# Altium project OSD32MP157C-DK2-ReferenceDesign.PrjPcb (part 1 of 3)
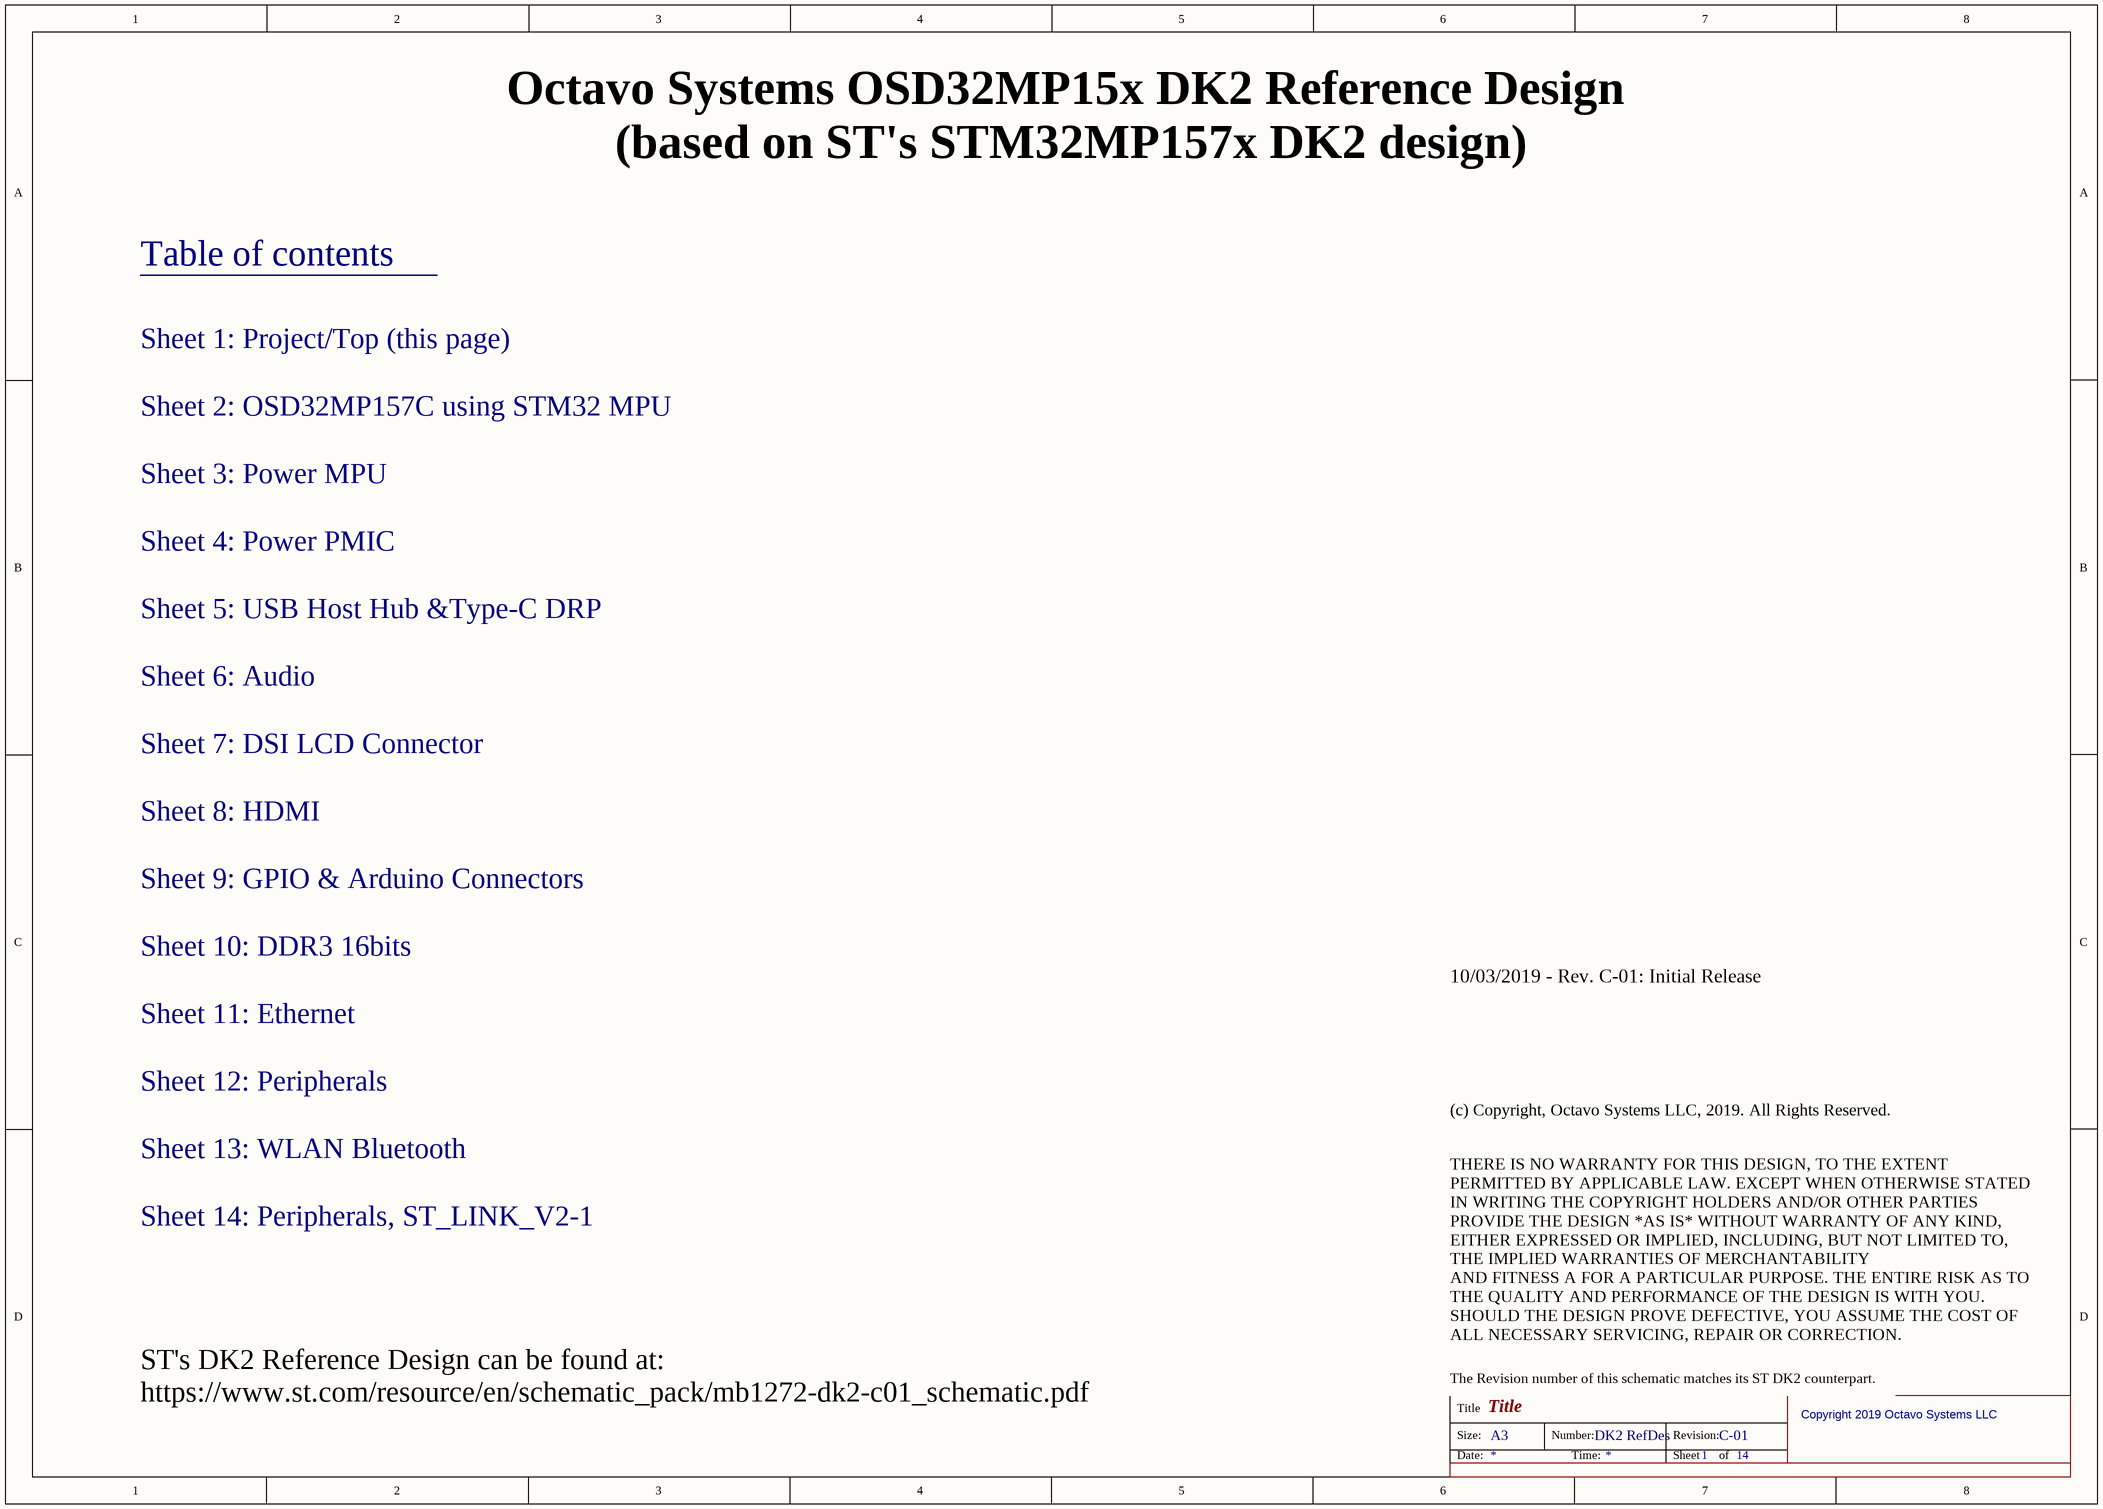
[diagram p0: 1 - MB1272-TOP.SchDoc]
14 sheets, 409 parts. Net scope: flat (ports and power ports of the same name join across sheets).
Board file: OSD32MP157C_DK2-0071_01232019RELEASE.PcbDoc
Sheets:
  1 - MB1272-TOP.SchDoc
  2 - OSD32MP157C_18x18.SchDoc
  3 - Power_MPU.SchDoc
  4 - PMIC.SchDoc
  5 - USB_Host_Hub&TypeC_DRP.SchDoc
  6 - AUDIO.SchDoc
  7 - DSI_LCD.SchDoc
  8 - HDMI.SchDoc
  9 - GPIO_&_Arduino_ Connectors.SchDoc
  10 - DDR3_16bits.SchDoc
  11 - Ethernet.SchDoc
  12 -  Peripherals.SchDoc
  13 - WLAN_BLUETOOTH.SchDoc
  14 -ST_LINK_V2-1.SCHDOC

## Sheet 1 - MB1272-TOP.SchDoc: Title
size A3; CompanyName: Octavo Systems; Address3: Austin, TX; Address4: USA; DocumentNumber: DK2 RefDes; Revision: C-01; SheetNumber: 1; SheetTotal: 14

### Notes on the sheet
- Octavo Systems OSD32MP15x DK2 Reference Design
  (based on ST's STM32MP157x DK2 design)
- Table of contents
- Sheet 1: Project/Top (this page)
- Sheet 2: OSD32MP157C using STM32 MPU
- Sheet 3: Power MPU
- Sheet 4: Power PMIC
- Sheet 5: USB Host Hub &Type-C DRP
- Sheet 6: Audio
- Sheet 7: DSI LCD Connector
- Sheet 8: HDMI
- Sheet 9: GPIO & Arduino Connectors
- Sheet 10: DDR3 16bits
- Sheet 11: Ethernet
- Sheet 12: Peripherals
- (c) Copyright, Octavo Systems LLC, 2019. All Rights Reserved.
- 10/03/2019 - Rev. C-01: Initial Release
- Sheet 13: WLAN Bluetooth
- Sheet 14: Peripherals, ST_LINK_V2-1
- THERE IS NO WARRANTY FOR THIS DESIGN, TO THE EXTENT PERMITTED BY APPLICABLE LAW. EXCEPT WHEN OTHERWISE STATED IN WRITING THE COPYRIGHT HOLDERS AND/OR OTHER PARTIES PROVIDE THE DESIGN *AS IS* WITHOUT WARRANTY OF ANY KIND, EITHER EXPRESSED OR IMPLIED, INCLUDING, BUT NOT LIMITED TO, THE IMPLIED WARRANTIES OF MERCHANTABILITY
  AND FITNESS A FOR A PARTICULAR PURPOSE. THE ENTIRE RISK AS TO THE QUALITY AND PERFORMANCE OF THE DESIGN IS WITH YOU. SHOULD THE DESIGN PROVE DEFECTIVE, YOU ASSUME THE COST OF ALL NECESSARY SERVICING, REPAIR OR CORRECTION.
- The Revision number of this schematic matches its ST DK2 counterpart.
- ST's DK2 Reference Design can be found at: https://www.st.com/resource/en/schematic_pack/mb1272-dk2-c01_schematic.pdf
- Copyright 2019 Octavo Systems LLC

## Sheet 2 - OSD32MP157C_18x18.SchDoc: MPU_18x18 IO
size A3; DocumentNumber: DK2 RefDes; Revision: C-01; SheetNumber: 2; SheetTotal: 14
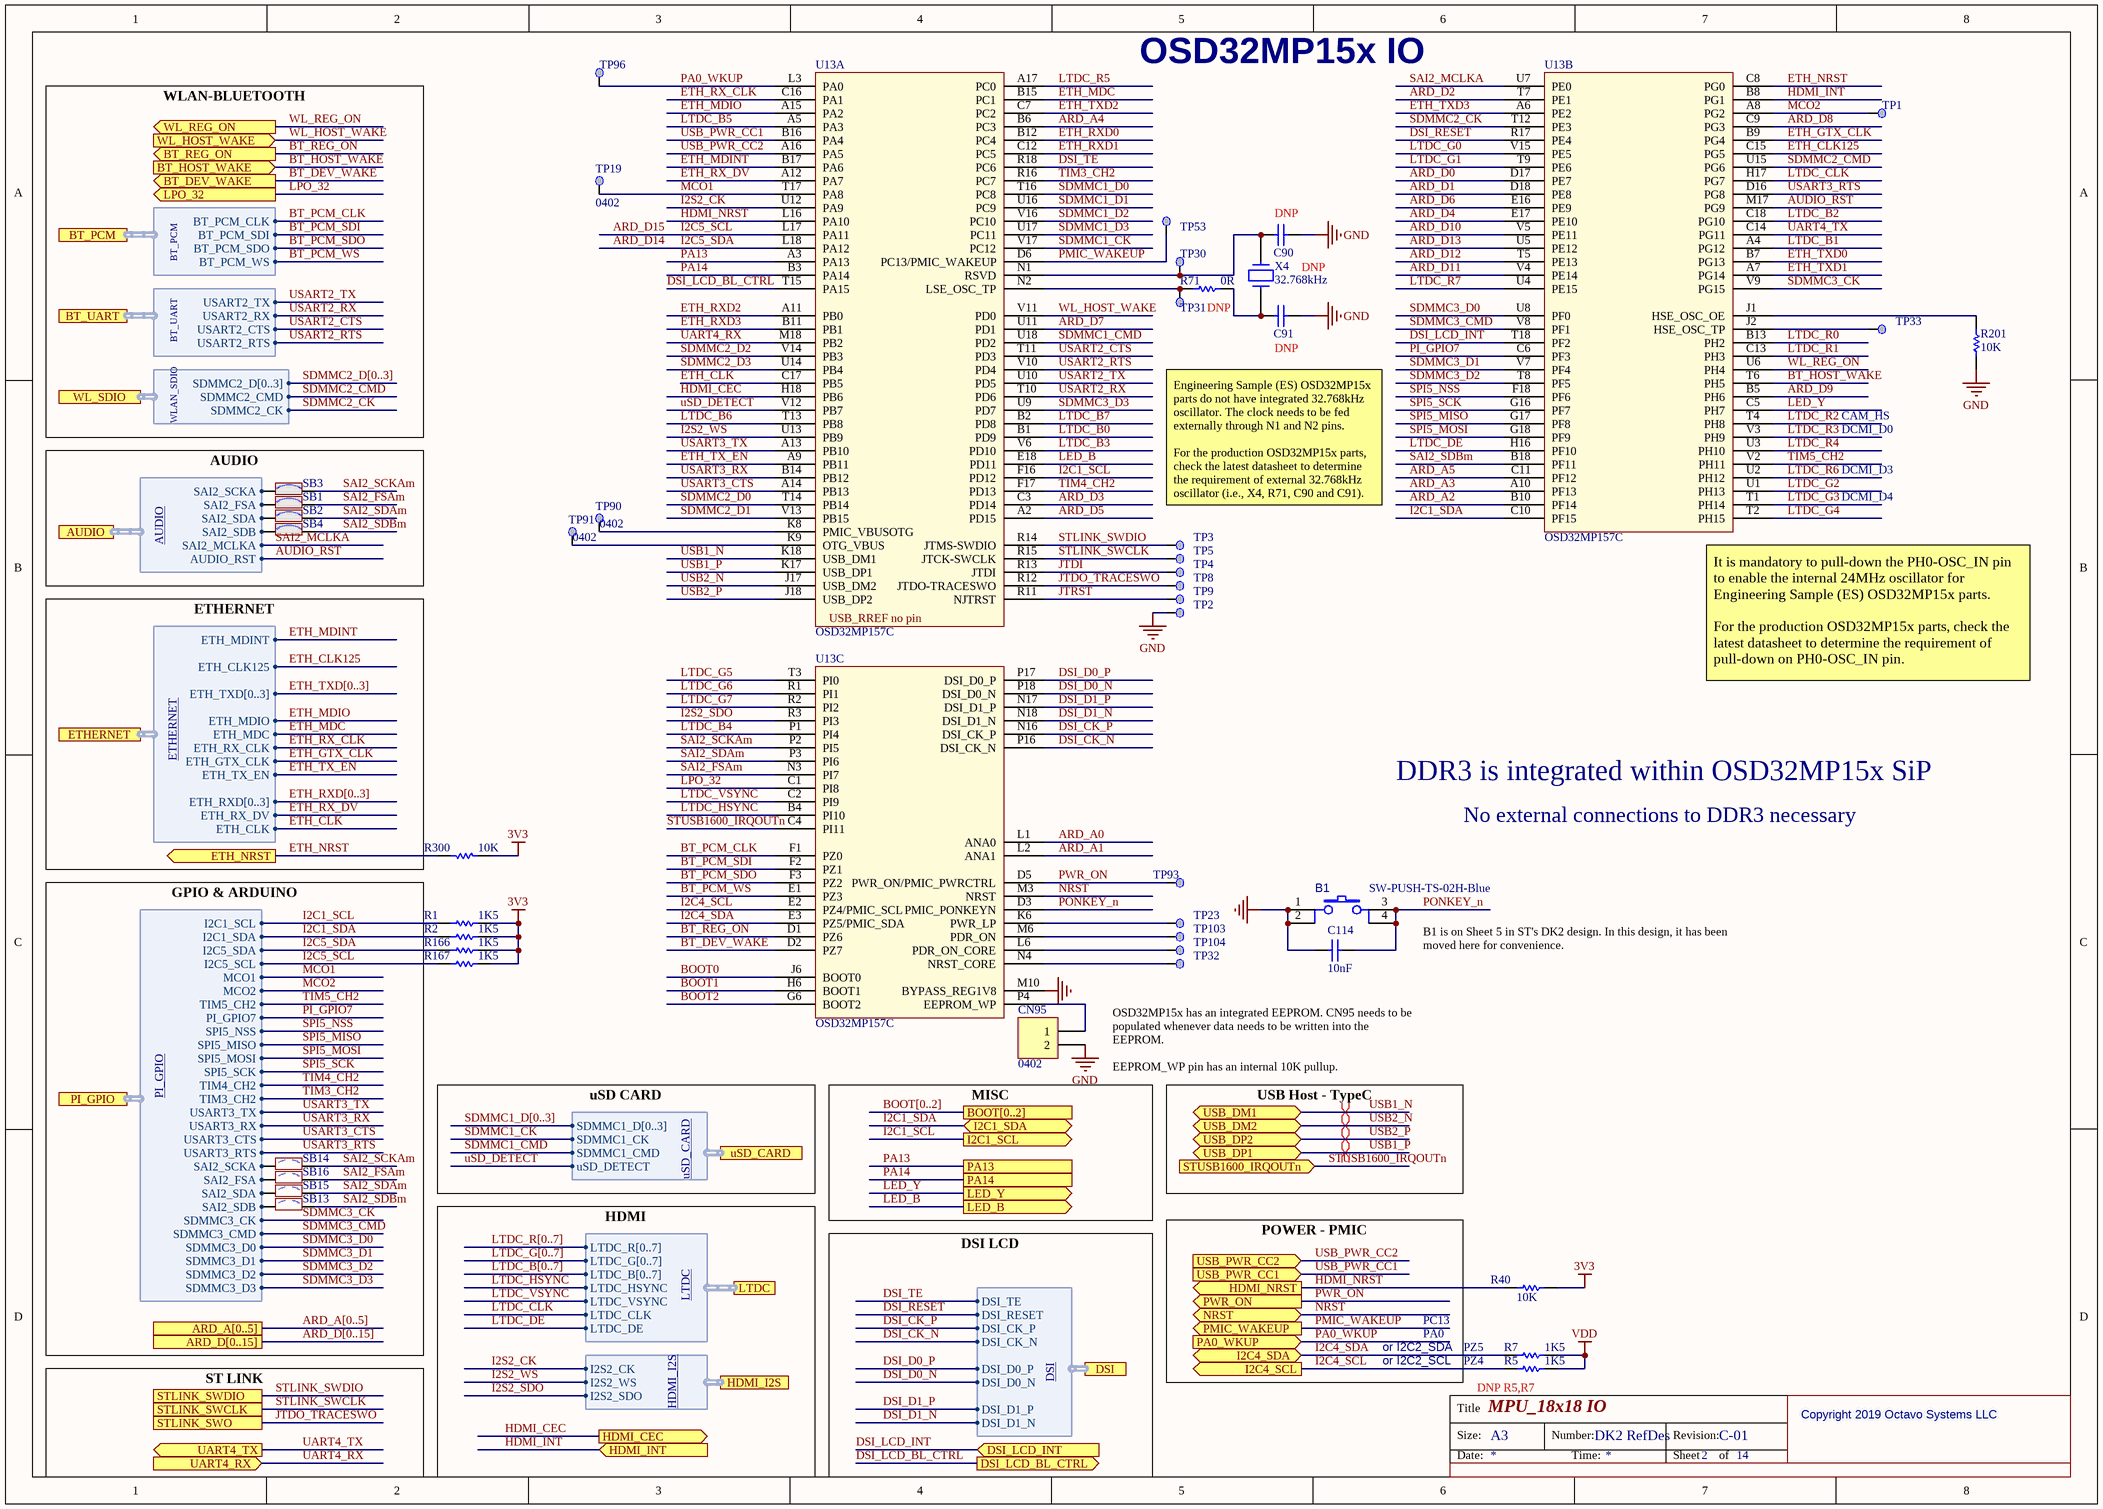
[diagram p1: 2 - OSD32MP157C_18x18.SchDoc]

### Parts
B1  value SW-PUSH-TS-02H-Blue  [SWI_JIUBABA_C-TS-02H-2-5-B-V-T_R_BLUE]
C90  Capacitor  [C0402]  (value not drawn)  (no BOM)
C91  Capacitor  [C0402]  (value not drawn)  (no BOM)
C114  value 10nF  [C0402]
CN95  0402  [MHDR1X2]
R1  value 1K5  [R0402]
R2  value 1K5  [R0402]
R5  value 1K5  [R0402]  (no BOM)
R7  value 1K5  [R0402]  (no BOM)
R40  value 10K  [R0402]  (hidden comment: Resistor)
R71  value 0R  [R0402]
R166  value 1K5  [R0402]
R167  value 1K5  [R0402]
R201  value 10K  [R0402]
R300  value 10K  [R0402]  (hidden comment: Resistor)
SB1  (no value)  [SOLDER-BRIDGE_R0603-0R]
SB2  (no value)  [SOLDER-BRIDGE_R0603-0R]
SB3  (no value)  [SOLDER-BRIDGE_R0603-0R]
SB4  (no value)  [SOLDER-BRIDGE_R0603-0R]
SB13  (no value)  [SOLDER-BRIDGE_R0603-0R]
SB14  (no value)  [SOLDER-BRIDGE_R0603-0R]
SB15  (no value)  [SOLDER-BRIDGE_R0603-0R]
SB16  (no value)  [SOLDER-BRIDGE_R0603-0R]
TP1  Test Point  [TP_SMD_1MM]  (value not drawn)  (no BOM)
TP2  Test Point  [TP_SMD_1MM]  (value not drawn)  (no BOM)
TP3  Test Point  [TP_SMD_1MM]  (value not drawn)  (no BOM)
TP4  Test Point  [TP_SMD_1MM]  (value not drawn)  (no BOM)
TP5  Test Point  [TP_SMD_1MM]  (value not drawn)  (no BOM)
TP8  Test Point  [TP_SMD_1MM]  (value not drawn)  (no BOM)
TP9  Test Point  [TP_SMD_1MM]  (value not drawn)  (no BOM)
TP19  0402  [TP]
TP23  Test Point  [TP_SMD_1MM]  (value not drawn)  (no BOM)
TP30  Test Point  [TP_SMD_1MM]  (value not drawn)  (no BOM)
TP31  Test Point  [TP_SMD_1MM]  (value not drawn)  (no BOM)
TP32  Test Point  [TP_SMD_1MM]  (value not drawn)  (no BOM)
TP33  Test Point  [TP_SMD_1MM]  (value not drawn)  (no BOM)
TP53  0402  [TP]  (value not drawn)
TP90  0402  [TP]
TP91  0402  [TP]
TP93  0402  [TP]  (value not drawn)
TP96  0402  [TP]  (value not drawn)
TP103  0402  [TP]  (value not drawn)
TP104  0402  [TP]  (value not drawn)
U13  OSD32MP157C  [ICC_BGA324_18X18_OSD32MP157CAC3]  (parts A,B,C of 4)
X4  value 32.768kHz  [CRY_NX2012SA_2P]

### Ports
ARD_A[0..5], ARD_D[0..15], AUDIO (harness AUDIO), BOOT[0..2], BT_DEV_WAKE (out), BT_HOST_WAKE (in), BT_PCM (harness BT_PCM), BT_REG_ON (out), BT_UART (harness BT_UART), DSI (harness DSI), DSI_LCD_BL_CTRL (out), DSI_LCD_INT (in), ETH_NRST (out), ETHERNET (harness ETHERNET), HDMI_CEC (out), HDMI_I2S (harness HDMI_I2S), HDMI_INT (in), HDMI_NRST (out), I2C1_SCL (out), I2C1_SDA (bidir), I2C4_SCL (out), I2C4_SDA (bidir), LED_B (out), LED_Y (out), LPO_32 (out), LTDC (harness LTDC), NRST (bidir), PA0_WKUP (in), PA13, PA14, PI_GPIO (harness PI_GPIO), PMIC_WAKEUP (out), PWR_ON (out), STLINK_SWCLK, STLINK_SWDIO, STLINK_SWO, STUSB1600_IRQOUTn (in), UART4_RX (in), UART4_TX (out), USB_DM1 (bidir), USB_DM2 (bidir), USB_DP1 (bidir), USB_DP2 (bidir), USB_PWR_CC1 (in), USB_PWR_CC2 (in), uSD_CARD (harness uSD_CARD), WL_HOST_WAKE (in), WL_REG_ON (out), WL_SDIO (harness WLAN_SDIO)

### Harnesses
PI_GPIO: I2C1_SCL, I2C1_SDA, I2C5_SDA, MCO1, MCO2, TIM5_CH2, PI_GPIO7, SPI5_NSS, SPI5_MISO, SPI5_MOSI, SPI5_SCK, TIM4_CH2, TIM3_CH2, USART3_TX, USART3_RX, USART3_CTS, USART3_RTS, SDMMC3_CK, SDMMC3_CMD, SDMMC3_D0, SDMMC3_D1, SDMMC3_D2, SDMMC3_D3, I2C5_SCL, SAI2_SCKA, SAI2_FSA, SAI2_SDA, SAI2_SDB
ETHERNET: ETH_MDINT, ETH_CLK125, ETH_TXD[0..3], ETH_MDIO, ETH_MDC, ETH_RX_CLK, ETH_GTX_CLK, ETH_TX_EN, ETH_RXD[0..3], ETH_RX_DV, ETH_CLK
AUDIO: SAI2_SCKA, SAI2_FSA, SAI2_SDA, SAI2_SDB, SAI2_MCLKA, AUDIO_RST
LTDC: LTDC_R[0..7], LTDC_G[0..7], LTDC_B[0..7], LTDC_HSYNC, LTDC_VSYNC, LTDC_CLK, LTDC_DE
uSD_CARD: SDMMC1_D[0..3], SDMMC1_CK, SDMMC1_CMD, uSD_DETECT
BT_PCM: BT_PCM_CLK, BT_PCM_SDI, BT_PCM_SDO, BT_PCM_WS
BT_UART: USART2_TX, USART2_RX, USART2_CTS, USART2_RTS
WLAN_SDIO: SDMMC2_D[0..3], SDMMC2_CMD, SDMMC2_CK
HDMI_I2S: I2S2_CK, I2S2_SDO, I2S2_WS
DSI: DSI_CK_P, DSI_CK_N, DSI_D0_P, DSI_D0_N, DSI_D1_P, DSI_D1_N, DSI_TE, DSI_RESET

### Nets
3V3: R1.1 R2.1 R40.1 R166.1 R167.1 R300.1
GND: B1.1 B1.2 C90.2 C91.2 C114.1 CN95.2 R201.1 TP2.1 U13.M10(BYPASS_REG1V8)
VDD: R5.1 R7.1
ARD_A0: U13.L1(ANA0)
ARD_A1: U13.L2(ANA1)
ARD_A2: U13.B10(PF14)
ARD_A3: U13.A10(PF13)
ARD_A4: U13.B6(PC3)
ARD_A5: U13.C11(PF12)
ARD_D0: U13.D17(PE7)
ARD_D1: U13.D18(PE8)
ARD_D2: U13.T7(PE1)
ARD_D3: U13.C3(PD14)
ARD_D4: U13.E17(PE10)
ARD_D5: U13.A2(PD15)
ARD_D6: U13.E16(PE9)
ARD_D7: U13.U11(PD1)
ARD_D8: U13.C9(PG3)
ARD_D9: U13.B5(PH6)
ARD_D10: U13.V5(PE11)
ARD_D11: U13.V4(PE14)
ARD_D12: U13.T5(PE13)
ARD_D13: U13.U5(PE12)
ARD_D14: R166.2 U13.L18(PA12) ; port PI_GPIO.I2C5_SDA  [also labelled I2C5_SDA]
ARD_D15: R167.2 U13.L17(PA11) ; port PI_GPIO.I2C5_SCL  [also labelled I2C5_SCL]
AUDIO_RST: U13.M17(PG9) ; port AUDIO.AUDIO_RST
BOOT0: U13.J6(BOOT0)
BOOT1: U13.H6(BOOT1)
BOOT2: U13.G6(BOOT2)
BT_DEV_WAKE: U13.D2(PZ7) ; port BT_DEV_WAKE
BT_HOST_WAKE: U13.T6(PH5) ; port BT_HOST_WAKE
BT_PCM_CLK: U13.F1(PZ0) ; port BT_PCM.BT_PCM_CLK
BT_PCM_SDI: U13.F2(PZ1) ; port BT_PCM.BT_PCM_SDI
BT_PCM_SDO: U13.F3(PZ2) ; port BT_PCM.BT_PCM_SDO
BT_PCM_WS: U13.E1(PZ3) ; port BT_PCM.BT_PCM_WS
BT_REG_ON: U13.D1(PZ6) ; port BT_REG_ON
DSI_CK_N: U13.P16(DSI_CK_N) ; port DSI.DSI_CK_N
DSI_CK_P: U13.N16(DSI_CK_P) ; port DSI.DSI_CK_P
DSI_D0_N: U13.P18(DSI_D0_N) ; port DSI.DSI_D0_N
DSI_D0_P: U13.P17(DSI_D0_P) ; port DSI.DSI_D0_P
DSI_D1_N: U13.N18(DSI_D1_N) ; port DSI.DSI_D1_N
DSI_D1_P: U13.N17(DSI_D1_P) ; port DSI.DSI_D1_P
DSI_LCD_BL_CTRL: U13.T15(PA15) ; port DSI_LCD_BL_CTRL
DSI_LCD_INT: U13.T18(PF2) ; port DSI_LCD_INT
DSI_RESET: U13.R17(PE4) ; port DSI.DSI_RESET
DSI_TE: U13.R18(PC6) ; port DSI.DSI_TE
ETH_CLK: U13.C17(PB5) ; port ETHERNET.ETH_CLK
ETH_CLK125: U13.C15(PG5) ; port ETHERNET.ETH_CLK125
ETH_GTX_CLK: U13.B9(PG4) ; port ETHERNET.ETH_GTX_CLK
ETH_MDC: U13.B15(PC1) ; port ETHERNET.ETH_MDC
ETH_MDINT: U13.B17(PA6) ; port ETHERNET.ETH_MDINT
ETH_MDIO: U13.A15(PA2) ; port ETHERNET.ETH_MDIO
ETH_NRST: R300.2 U13.C8(PG0) ; port ETH_NRST
ETH_RX_CLK: U13.C16(PA1) ; port ETHERNET.ETH_RX_CLK
ETH_RX_DV: U13.A12(PA7) ; port ETHERNET.ETH_RX_DV
ETH_RXD0: U13.B12(PC4)
ETH_RXD1: U13.C12(PC5)
ETH_RXD2: U13.A11(PB0)
ETH_RXD3: U13.B11(PB1)
ETH_TX_EN: U13.A9(PB11) ; port ETHERNET.ETH_TX_EN
ETH_TXD0: U13.B7(PG13)
ETH_TXD1: U13.A7(PG14)
ETH_TXD2: U13.C7(PC2)
ETH_TXD3: U13.A6(PE2)
EXP_GPIO18: SB14.1 ; port PI_GPIO.SAI2_SCKA
EXP_GPIO19: SB16.1 ; port PI_GPIO.SAI2_FSA
EXP_GPIO20: SB15.1 ; port PI_GPIO.SAI2_SDA
EXP_GPIO21: SB13.1 ; port PI_GPIO.SAI2_SDB
HDMI_CEC: U13.H18(PB6) ; port HDMI_CEC
HDMI_INT: U13.B8(PG1) ; port HDMI_INT
HDMI_NRST: R40.2 U13.L16(PA10) ; port HDMI_NRST
I2C1_SCL: R1.2 U13.F16(PD12) ; port I2C1_SCL, port PI_GPIO.I2C1_SCL
I2C1_SDA: R2.2 U13.C10(PF15) ; port I2C1_SDA, port PI_GPIO.I2C1_SDA
I2C4_SCL: R5.2 U13.E2(PZ4/PMIC_SCL) ; port I2C4_SCL
I2C4_SDA: R7.2 U13.E3(PZ5/PMIC_SDA) ; port I2C4_SDA
I2S2_CK: U13.U12(PA9) ; port HDMI_I2S.I2S2_CK
I2S2_SDO: U13.R3(PI3) ; port HDMI_I2S.I2S2_SDO
I2S2_WS: U13.U13(PB9) ; port HDMI_I2S.I2S2_WS
JTDI: TP4.1 U13.R13(JTDI)
JTDO_TRACESWO: TP8.1 U13.R12(JTDO-TRACESWO) ; port STLINK_SWO
JTRST: TP9.1 U13.R11(NJTRST)
LED_B: U13.E18(PD11) ; port LED_B
LED_Y: U13.C5(PH7) ; port LED_Y
LPO_32: U13.C1(PI8) ; port LPO_32
LTDC_B0: U13.B1(PD9)
LTDC_B1: U13.A4(PG12)
LTDC_B2: U13.C18(PG10)
LTDC_B3: U13.V6(PD10)
LTDC_B4: U13.P1(PI4)
LTDC_B5: U13.A5(PA3)
LTDC_B6: U13.T13(PB8)
LTDC_B7: U13.B2(PD8)
LTDC_CLK: U13.H17(PG7) ; port LTDC.LTDC_CLK
LTDC_DE: U13.H16(PF10) ; port LTDC.LTDC_DE
LTDC_G0: U13.V15(PE5)
LTDC_G1: U13.T9(PE6)
LTDC_G2: U13.U1(PH13)
LTDC_G3: U13.T1(PH14)
LTDC_G4: U13.T2(PH15)
LTDC_G5: U13.T3(PI0)
LTDC_G6: U13.R1(PI1)
LTDC_G7: U13.R2(PI2)
LTDC_HSYNC: U13.B4(PI10) ; port LTDC.LTDC_HSYNC
LTDC_R0: U13.B13(PH2)
LTDC_R1: U13.C13(PH3)
LTDC_R2: U13.T4(PH8)
LTDC_R3: U13.V3(PH9)
LTDC_R4: U13.U3(PH10)
LTDC_R5: U13.A17(PC0)
LTDC_R6: U13.U2(PH12)
LTDC_R7: U13.U4(PE15)
LTDC_VSYNC: U13.C2(PI9) ; port LTDC.LTDC_VSYNC
MCO1: TP19.1 U13.T17(PA8) ; port PI_GPIO.MCO1  [project net EXP_GPIO4]
MCO2: TP1.1 U13.A8(PG2) ; port PI_GPIO.MCO2  [project net EXP_GPIO5]
NRST: U13.M3(NRST) ; port NRST
PA0_WKUP: TP96.1 U13.L3(PA0) ; port PA0_WKUP
PA13: U13.A3(PA13) ; port PA13
PA14: U13.B3(PA14) ; port PA14
PI_GPIO7: U13.C6(PF3) ; port PI_GPIO.PI_GPIO7  [project net EXP_GPIO7]
PMIC_WAKEUP: TP53.1 U13.D6(PC13/PMIC_WAKEUP) ; port PMIC_WAKEUP
PONKEY_n: B1.3 B1.4 C114.2 U13.D3(PMIC_PONKEYN)
PWR_ON: TP93.1 U13.D5(PWR_ON/PMIC_PWRCTRL) ; port PWR_ON
SAI2_FSA: SB1.1 ; port AUDIO.SAI2_FSA
SAI2_FSAm: SB1.2 SB16.2 U13.N3(PI7)
SAI2_MCLKA: U13.U7(PE0) ; port AUDIO.SAI2_MCLKA
SAI2_SCKA: SB3.1 ; port AUDIO.SAI2_SCKA
SAI2_SCKAm: SB3.2 SB14.2 U13.P2(PI5)
SAI2_SDA: SB2.1 ; port AUDIO.SAI2_SDA
SAI2_SDAm: SB2.2 SB15.2 U13.P3(PI6)
SAI2_SDB: SB4.1 ; port AUDIO.SAI2_SDB
SAI2_SDBm: SB4.2 SB13.2 U13.B18(PF11)
SDMMC1_CK: U13.V17(PC12) ; port uSD_CARD.SDMMC1_CK
SDMMC1_CMD: U13.U18(PD2) ; port uSD_CARD.SDMMC1_CMD
SDMMC1_D0: U13.T16(PC8)
SDMMC1_D1: U13.U16(PC9)
SDMMC1_D2: U13.V16(PC10)
SDMMC1_D3: U13.U17(PC11)
SDMMC2_CK: U13.T12(PE3) ; port WL_SDIO.SDMMC2_CK
SDMMC2_CMD: U13.U15(PG6) ; port WL_SDIO.SDMMC2_CMD
SDMMC2_D0: U13.T14(PB14)
SDMMC2_D1: U13.V13(PB15)
SDMMC2_D2: U13.V14(PB3)
SDMMC2_D3: U13.U14(PB4)
SDMMC3_CK: U13.V9(PG15) ; port PI_GPIO.SDMMC3_CK  [project net EXP_GPIO22]
SDMMC3_CMD: U13.V8(PF1) ; port PI_GPIO.SDMMC3_CMD  [project net EXP_GPIO23]
SDMMC3_D0: U13.U8(PF0) ; port PI_GPIO.SDMMC3_D0  [project net EXP_GPIO24]
SDMMC3_D1: U13.V7(PF4) ; port PI_GPIO.SDMMC3_D1  [project net EXP_GPIO25]
SDMMC3_D2: U13.T8(PF5) ; port PI_GPIO.SDMMC3_D2  [project net EXP_GPIO26]
SDMMC3_D3: U13.U9(PD7) ; port PI_GPIO.SDMMC3_D3  [project net EXP_GPIO27]
SPI5_MISO: U13.G17(PF8) ; port PI_GPIO.SPI5_MISO  [project net EXP_GPIO9]
SPI5_MOSI: U13.G18(PF9) ; port PI_GPIO.SPI5_MOSI  [project net EXP_GPIO10]
SPI5_NSS: U13.F18(PF6) ; port PI_GPIO.SPI5_NSS  [project net EXP_GPIO8]
SPI5_SCK: U13.G16(PF7) ; port PI_GPIO.SPI5_SCK  [project net EXP_GPIO11]
STLINK_SWCLK: TP5.1 U13.R15(JTCK-SWCLK) ; port STLINK_SWCLK
STLINK_SWDIO: TP3.1 U13.R14(JTMS-SWDIO) ; port STLINK_SWDIO
STUSB1600_IRQOUTn: U13.C4(PI11) ; port STUSB1600_IRQOUTn
TIM3_CH2: U13.R16(PC7) ; port PI_GPIO.TIM3_CH2  [project net EXP_GPIO13]
TIM4_CH2: U13.F17(PD13) ; port PI_GPIO.TIM4_CH2  [project net EXP_GPIO12]
TIM5_CH2: U13.V2(PH11) ; port PI_GPIO.TIM5_CH2  [project net EXP_GPIO6]
UART4_RX: U13.M18(PB2) ; port UART4_RX
UART4_TX: U13.C14(PG11) ; port UART4_TX
USART2_CTS: U13.T11(PD3) ; port BT_UART.USART2_CTS
USART2_RTS: U13.V10(PD4) ; port BT_UART.USART2_RTS
USART2_RX: U13.T10(PD6) ; port BT_UART.USART2_RX
USART2_TX: U13.U10(PD5) ; port BT_UART.USART2_TX
USART3_CTS: U13.A14(PB13) ; port PI_GPIO.USART3_CTS  [project net EXP_GPIO16]
USART3_RTS: U13.D16(PG8) ; port PI_GPIO.USART3_RTS  [project net EXP_GPIO17]
USART3_RX: U13.B14(PB12) ; port PI_GPIO.USART3_RX  [project net EXP_GPIO15]
USART3_TX: U13.A13(PB10) ; port PI_GPIO.USART3_TX  [project net EXP_GPIO14]
USB1_N: U13.K18(USB_DM1) ; port USB_DM1
USB1_P: U13.K17(USB_DP1) ; port USB_DP1
USB2_N: U13.J17(USB_DM2) ; port USB_DM2
USB2_P: U13.J18(USB_DP2) ; port USB_DP2
USB_PWR_CC1: U13.B16(PA4) ; port USB_PWR_CC1
USB_PWR_CC2: U13.A16(PA5) ; port USB_PWR_CC2
uSD_DETECT: U13.V12(PB7) ; port uSD_CARD.uSD_DETECT
WL_HOST_WAKE: U13.V11(PD0) ; port WL_HOST_WAKE
WL_REG_ON: U13.U6(PH4) ; port WL_REG_ON
NetC90_1: C90.1 TP30.1 U13.N1(RSVD) X4.1
NetC91_1: C91.1 R71.2 X4.2
NetCN95_1: CN95.1 U13.P4(EEPROM_WP)
NetR71_1: R71.1 TP31.1 U13.N2(LSE_OSC_TP)
NetR201_2: R201.2 U13.J1(HSE_OSC_OE)
NetTP23_1: TP23.1 U13.K6(PWR_LP)
NetTP32_1: TP32.1 U13.N4(NRST_CORE)
NetTP33_1: TP33.1 U13.J2(HSE_OSC_TP)
NetTP90_1: TP90.1 U13.K8(PMIC_VBUSOTG)
NetTP91_1: TP91.1 U13.K9(OTG_VBUS)
NetTP103_1: TP103.1 U13.M6(PDR_ON)
NetTP104_1: TP104.1 U13.L6(PDR_ON_CORE)

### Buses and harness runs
bus ARD_A[0..5] = port ARD_A[0..5]
bus ARD_D[0..15] = port ARD_D[0..15]
bus BOOT[0..2] = port BOOT[0..2]
bus ETH_RXD[0..3]
bus ETH_TXD[0..3]
bus LTDC_B[0..7]
bus LTDC_G[0..7]
bus LTDC_R[0..7]
bus SDMMC1_D[0..3]
bus SDMMC2_D[0..3]

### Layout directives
differential pair: USB1_N, USB1_P, USB2_N, USB2_P

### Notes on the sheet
- OSD32MP15x IO
- (near C90) DNP
- (near R71) DNP
- DNP
- (near C91) DNP
- WLAN-BLUETOOTH
- DCMI_D0
- CAM_HS
- Engineering Sample (ES) OSD32MP15x parts do not have integrated 32.768kHz oscillator. The clock needs to be fed externally through N1 and N2 pins.
  For the production OSD32MP15x parts, check the latest datasheet to determine the requirement of external 32.768kHz oscillator (i.e., X4, R71, C90 and C91).
- DCMI_D3
- DCMI_D4
- AUDIO
- (near U13) It is mandatory to pull-down the PH0-OSC_IN pin to enable the internal 24MHz oscillator for Engineering Sample (ES) OSD32MP15x parts.
  For the production OSD32MP15x parts, check the latest datasheet to determine the requirement of  pull-down on PH0-OSC_IN pin.
- DDR3 is integrated within OSD32MP15x SiP
- No external connections to DDR3 necessary
- (near R300) ETHERNET
- B1 is on Sheet 5 in ST's DK2 design. In this design, it has been moved here for convenience.
- OSD32MP15x has an integrated EEPROM. CN95 needs to be populated whenever data needs to be written into the EEPROM.
  EEPROM_WP pin has an internal 10K pullup.
- uSD CARD
- USB Host - TypeC
- (near CN95) MISC
- PC13
- GPIO & ARDUINO
- POWER - PMIC
- or I2C2_SDA
- or I2C2_SCL
- PA0
- PZ5
- PZ4
- (near R5) DNP R5,R7
- Copyright 2019 Octavo Systems LLC
- ST LINK
- HDMI
- DSI LCD

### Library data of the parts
B1 = MCD-00172: Switch HW SMD blue; Part_Type: Misc; Manufacturer_Part_Number: C-TS-02H-2.5-B-V-T/R BLUE; Manufacturer: JIUBABA; Provided_By: Subcon; Initial_Board_Reference: MB1264
C90 C91 = MCD-00200: Capacitor, MLCC, 12pF, 50V, NPO, 5%, 0402, T=0,5mm; Manufacturer_Part_Number: CC0402JRNPO9BN120; Manufacturer: YAGEO; Provided_By: Subcon
C114 = MCD-00011: Capacitor, MLCC, 10nF, 16V, X7R, 10%, 0402, T=0.5mm; Manufacturer_Part_Number: CC0402KRX7R7BB103; Manufacturer: YAGEO; Provided_By: Subcon; Initial_Board_Reference: mb1274
CN95 = MHDR1x2: Header, 2-Pin, 50 mil
R1 R2 R5 R7 R166 R167 = MCD-00068: Resistor,1K5,0402,1%,1/16W; Manufacturer_Part_Number: RC0402FR-071K5L; Manufacturer: YAGEO; Provided_By: Subcon; Initial_Board_Reference: mb1274
R40 R300 = MCD-00053: Resistor,10K,0402,1%,1/16W; Manufacturer_Part_Number: RC0402FR-0710KL; Manufacturer: YAGEO; Provided_By: subcon; Initial_Board_Reference: MB1274
R71 = MCD-00052: Resistor,0R,0402,5%,1/16W; Manufacturer_Part_Number: RC0402JR-070RL; Manufacturer: YAGEO; Provided_By: Subcon; Initial_Board_Reference: mb1274
R201 = MCD-00185: Resistor,3K,0402,1%,1/16W; Manufacturer_Part_Number: RC0402FR-073KL; Manufacturer: YAGEO; Provided_By: Subcon
SB1-SB4 = MCD-00071: Solder Bridge ON; Part_Type: Mechanical; Provided_By: Subcon; Initial_Board_Reference: mb1274
SB13-SB16 = MCD-00072: Solder Bridge OFF; Part_Type: Mechanical; Initial_Board_Reference: mb1274
TP1-TP5 TP8 TP9 TP23 TP30-TP33 = MCD-00074: Test Point 1mm; Part_Type: Mechanical; Initial_Board_Reference: MB1274
TP19 TP53 TP90 TP91 TP93 TP96 TP103 TP104 = TP: Testpoint
U13 = OSD32MP157C: MPU 18x18 SIP; Part_Type: IC; Manufacturer: Octavo; ECCN_US: TBD
X4 = MCD-00292: Surface mount Crystal 32.768kHz, 12.5pF; Manufacturer_Part_Number: NX2012SA 32.768kHz EXS00A-MU00528; Part_Type: Crystal_Osc; Manufacturer: NDK; Provided_By: Subcon; Initial_Board_Reference: MB1263

## Sheet 3 - Power_MPU.SchDoc: Power_MPU
size A3; CompanyName: Octavo Systtems LLC; Address3: Austin,TX; Address4: USA; DocumentNumber: DK2 RefDes; Revision: C-01; SheetNumber: 3; SheetTotal: 14
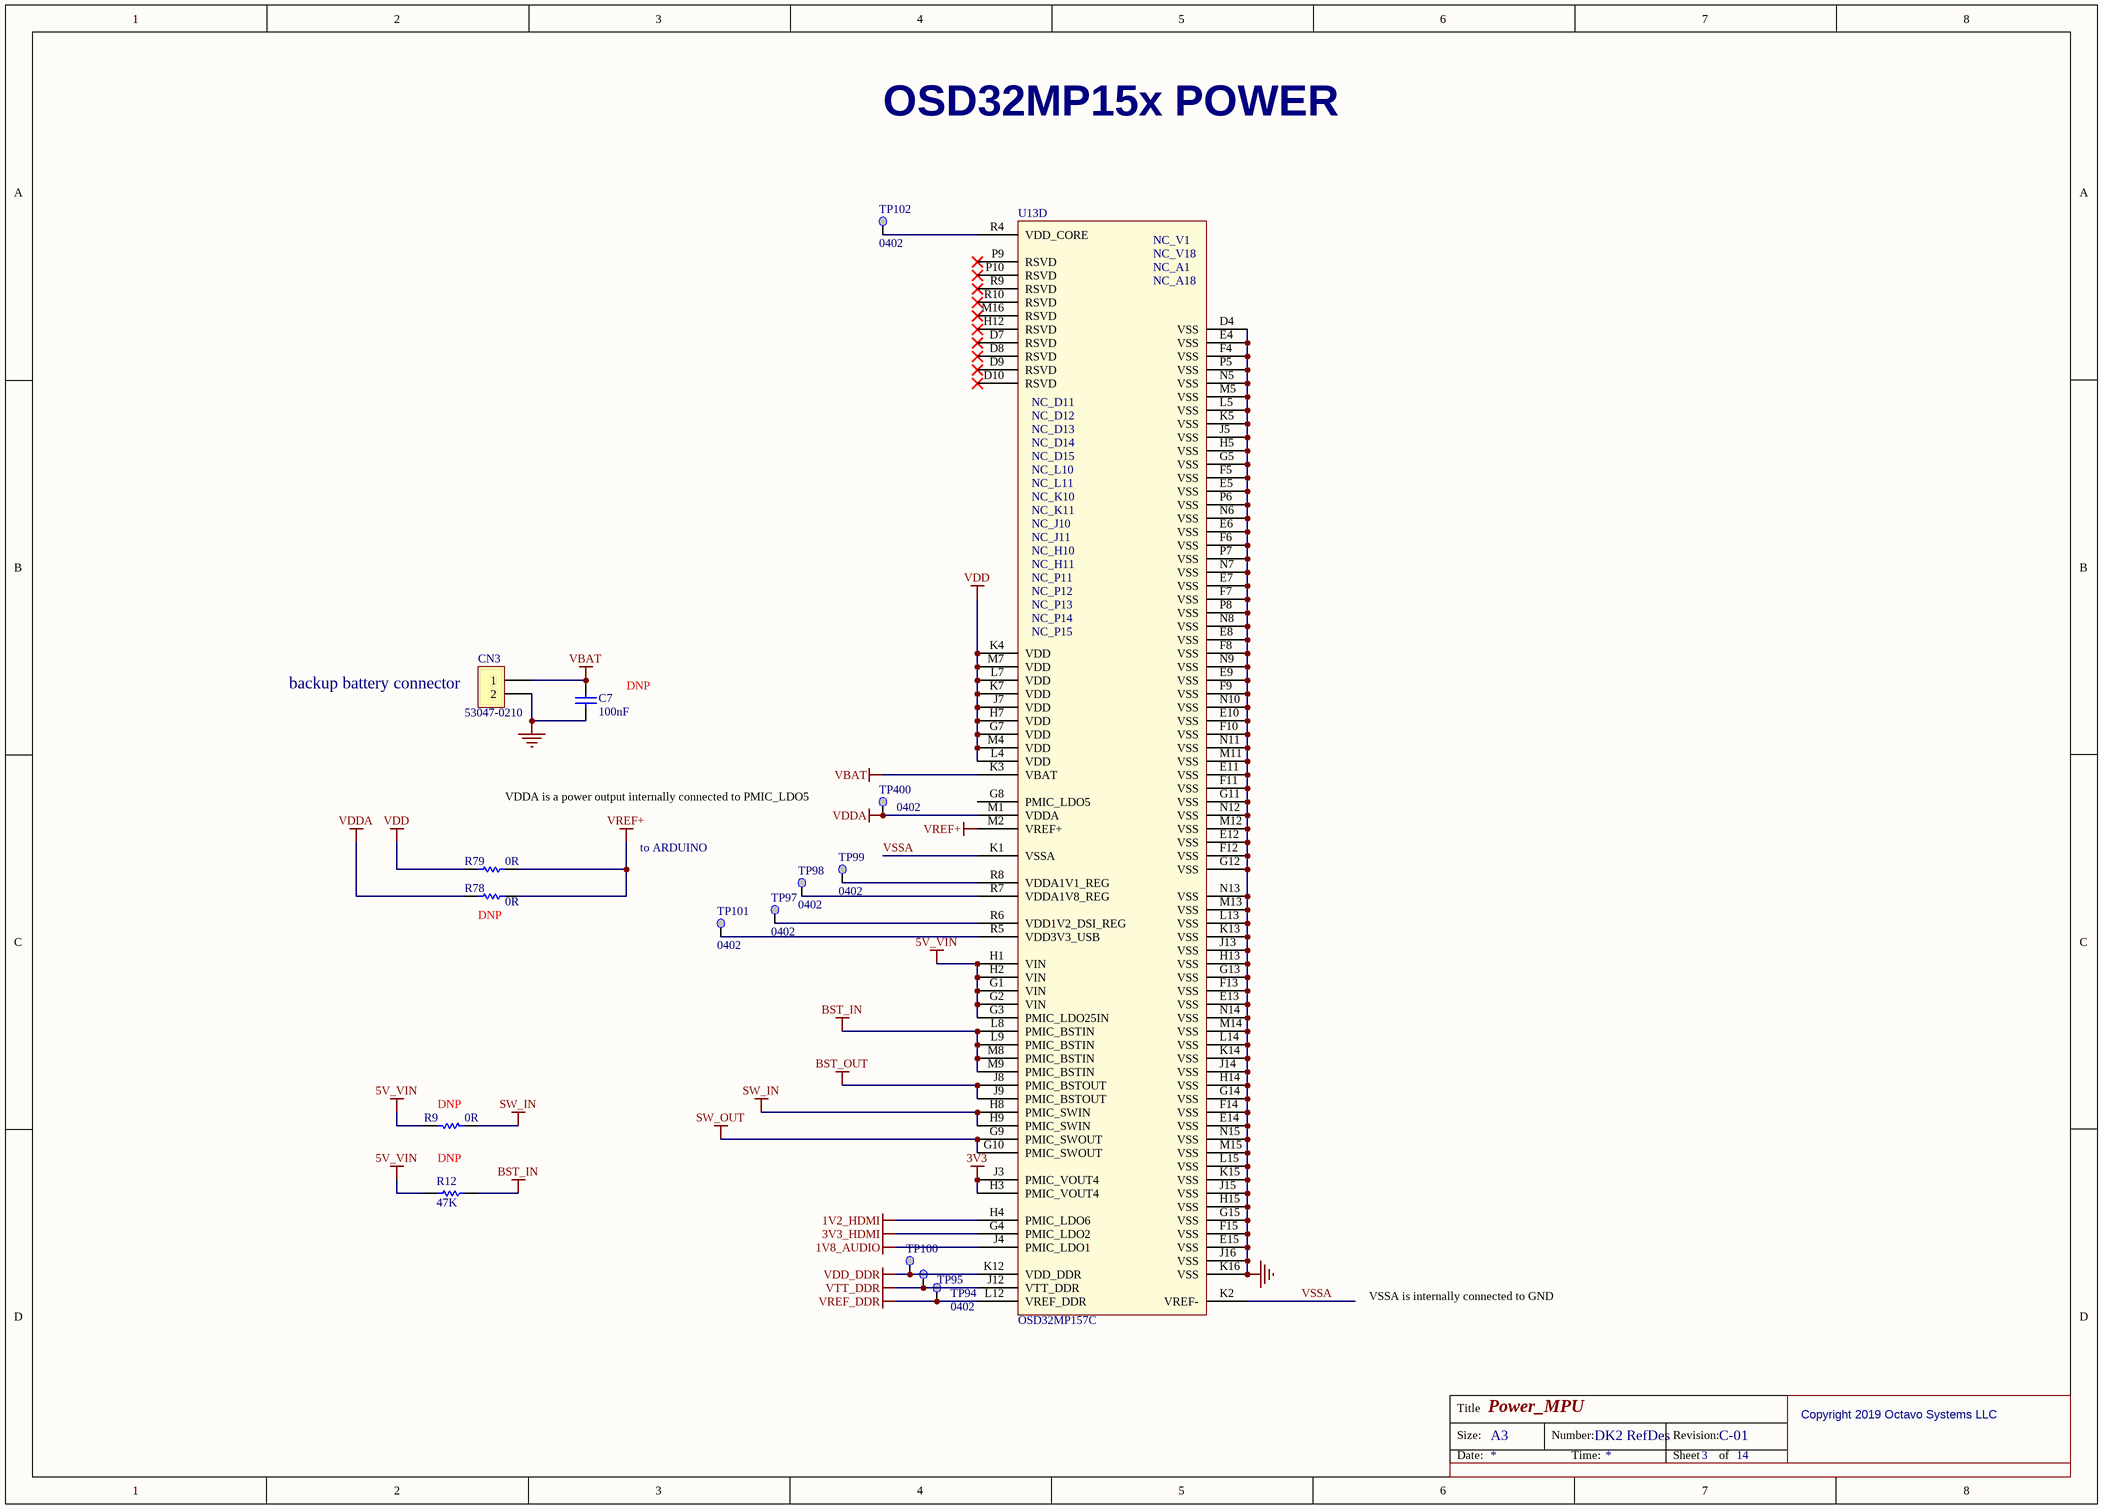
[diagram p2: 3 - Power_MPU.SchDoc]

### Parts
C7  value 100nF  [C0402]  (no BOM)
CN3  value 53047-0210  [CON_MOLEX_53047-0210]
R9  value 0R  [R0402]  (no BOM)
R12  value 47K  [R0402]  (hidden comment: Resistor)  (no BOM)
R78  value 0R  [R0402]  (no BOM)
R79  value 0R  [R0402]
TP94  0402  [TP]
TP95  0402  [TP]  (value not drawn)
TP97  0402  [TP]
TP98  0402  [TP]
TP99  0402  [TP]
TP100  0402  [TP]  (value not drawn)
TP101  0402  [TP]
TP102  0402  [TP]
TP400  0402  [TP]
U13  OSD32MP157C  [ICC_BGA324_18X18_OSD32MP157CAC3]  (part D of 4)

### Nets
1V2_HDMI: U13.H4(PMIC_LDO6)
1V8_AUDIO: U13.J4(PMIC_LDO1)
3V3: U13.H3(PMIC_VOUT4) U13.J3(PMIC_VOUT4)
3V3_HDMI: U13.G4(PMIC_LDO2)
5V_VIN: R9.1 R12.2 U13.G1(VIN) U13.G2(VIN) U13.G3(PMIC_LDO25IN) U13.H1(VIN) U13.H2(VIN)
BST_IN: R12.1 U13.L8(PMIC_BSTIN) U13.L9(PMIC_BSTIN) U13.M8(PMIC_BSTIN) U13.M9(PMIC_BSTIN)
BST_OUT: U13.J8(PMIC_BSTOUT) U13.J9(PMIC_BSTOUT)
GND: C7.1 CN3.2 U13.D4(VSS) U13.E4(VSS) U13.E5(VSS) U13.E6(VSS) U13.E7(VSS) U13.E8(VSS) U13.E9(VSS) U13.E10(VSS) U13.E11(VSS) U13.E12(VSS) U13.E13(VSS) U13.E14(VSS) U13.E15(VSS) U13.F4(VSS) U13.F5(VSS) U13.F6(VSS) U13.F7(VSS) U13.F8(VSS) U13.F9(VSS) U13.F10(VSS) U13.F11(VSS) U13.F12(VSS) U13.F13(VSS) U13.F14(VSS) U13.F15(VSS) U13.G5(VSS) U13.G11(VSS) U13.G12(VSS) U13.G13(VSS) U13.G14(VSS) U13.G15(VSS) U13.H5(VSS) U13.H13(VSS) U13.H14(VSS) U13.H15(VSS) U13.J5(VSS) U13.J13(VSS) U13.J14(VSS) U13.J15(VSS) U13.J16(VSS) U13.K5(VSS) U13.K13(VSS) U13.K14(VSS) U13.K15(VSS) U13.K16(VSS) U13.L5(VSS) U13.L13(VSS) U13.L14(VSS) U13.L15(VSS) U13.M5(VSS) U13.M11(VSS) U13.M12(VSS) U13.M13(VSS) U13.M14(VSS) U13.M15(VSS) U13.N5(VSS) U13.N6(VSS) U13.N7(VSS) U13.N8(VSS) U13.N9(VSS) U13.N10(VSS) U13.N11(VSS) U13.N12(VSS) U13.N13(VSS) U13.N14(VSS) U13.N15(VSS) U13.P5(VSS) U13.P6(VSS) U13.P7(VSS) U13.P8(VSS)
SW_IN: R9.2 U13.H8(PMIC_SWIN) U13.H9(PMIC_SWIN)
SW_OUT: U13.G9(PMIC_SWOUT) U13.G10(PMIC_SWOUT)
VBAT: C7.2 CN3.1 U13.K3(VBAT)
VDD: R79.1 U13.G7(VDD) U13.H7(VDD) U13.J7(VDD) U13.K4(VDD) U13.K7(VDD) U13.L4(VDD) U13.L7(VDD) U13.M4(VDD) U13.M7(VDD)
VDD_DDR: TP100.1 U13.K12(VDD_DDR)
VDDA: R78.1 TP400.1 U13.M1(VDDA)
VREF+: R78.2 R79.2 U13.M2(VREF+)
VREF_DDR: TP94.1 U13.L12(VREF_DDR)
VTT_DDR: TP95.1 U13.J12(VTT_DDR)
VSSA: U13.K1(VSSA) U13.K2(VREF-)
NetTP97_1: TP97.1 U13.R6(VDD1V2_DSI_REG)
NetTP98_1: TP98.1 U13.R7(VDDA1V8_REG)
NetTP99_1: TP99.1 U13.R8(VDDA1V1_REG)
NetTP101_1: TP101.1 U13.R5(VDD3V3_USB)
NetTP102_1: TP102.1 U13.R4(VDD_CORE)

Not connected (* = marked no-connect by the designer): U13 D7(RSVD)* D8(RSVD)* D9(RSVD)* D10(RSVD)* G8(PMIC_LDO5) H12(RSVD)* M16(RSVD)* P9(RSVD)* P10(RSVD)* R9(RSVD)* R10(RSVD)*

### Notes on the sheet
- OSD32MP15x POWER
- (near CN3) backup battery connector
- (near C7) DNP
- VDDA is a power output internally connected to PMIC_LDO5
- to ARDUINO
- (near R78) DNP
- (near R9) DNP
- DNP
- VSSA is internally connected to GND
- Copyright 2019 Octavo Systems LLC

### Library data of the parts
C7 = MCD-00006: Capacitor,100nF,16V,X7R,10%,0402; Manufacturer_Part_Number: CC0402KRX7R7BB104; Manufacturer: YAGEO; Provided_By: Subcon; Initial_Board_Reference: MB1274
CN3 = MCD-00655: Header 2 circuits, 1.25mm Pitch ,  Vertical, with Friction Lock; Part_Type: Connector; Manufacturer: MOLEX; Provided_By: Subcon; Initial_Board_Reference: MB1272
R9 = MCD-00052: as R71 on sheet 2 - OSD32MP157C_18x18
R12 = MCD-00063: Resistor,47K,0402,1%,1/16W; Manufacturer_Part_Number: RC0402FR-0747KL; Manufacturer: YAGEO; Provided_By: Subcon; Initial_Board_Reference: MB1274
R78 = MCD-00052: Resistor,0R,0402,5%,1/16W; Manufacturer_Part_Number: RC0402JR-070RL; Manufacturer: YAGEO; Provided_By: Subcon; Initial_Board_Reference: MB1274
R79 = MCD-00052: Resistor,0R,0402,5%,1/16W; Manufacturer_Part_Number: RC0402JR-070RL; Manufacturer: YAGEO; Provided_By: Subcon; Initial_Board_Reference: MB1274; Fitted: NO
TP94 TP95 TP97-TP102 TP400 = TP: Testpoint
U13 = OSD32MP157C: as U13 on sheet 2 - OSD32MP157C_18x18

## Sheet 4 - PMIC.SchDoc: Power_PMIC
size A3; Date: 01-DEC-2018; CompanyName: Octavo Systems LLC; Address2: AUSTIN,TX; Address3: USA; DocumentNumber: DK2 RefDes; Revision: C-01; SheetNumber: 4; SheetTotal: 14
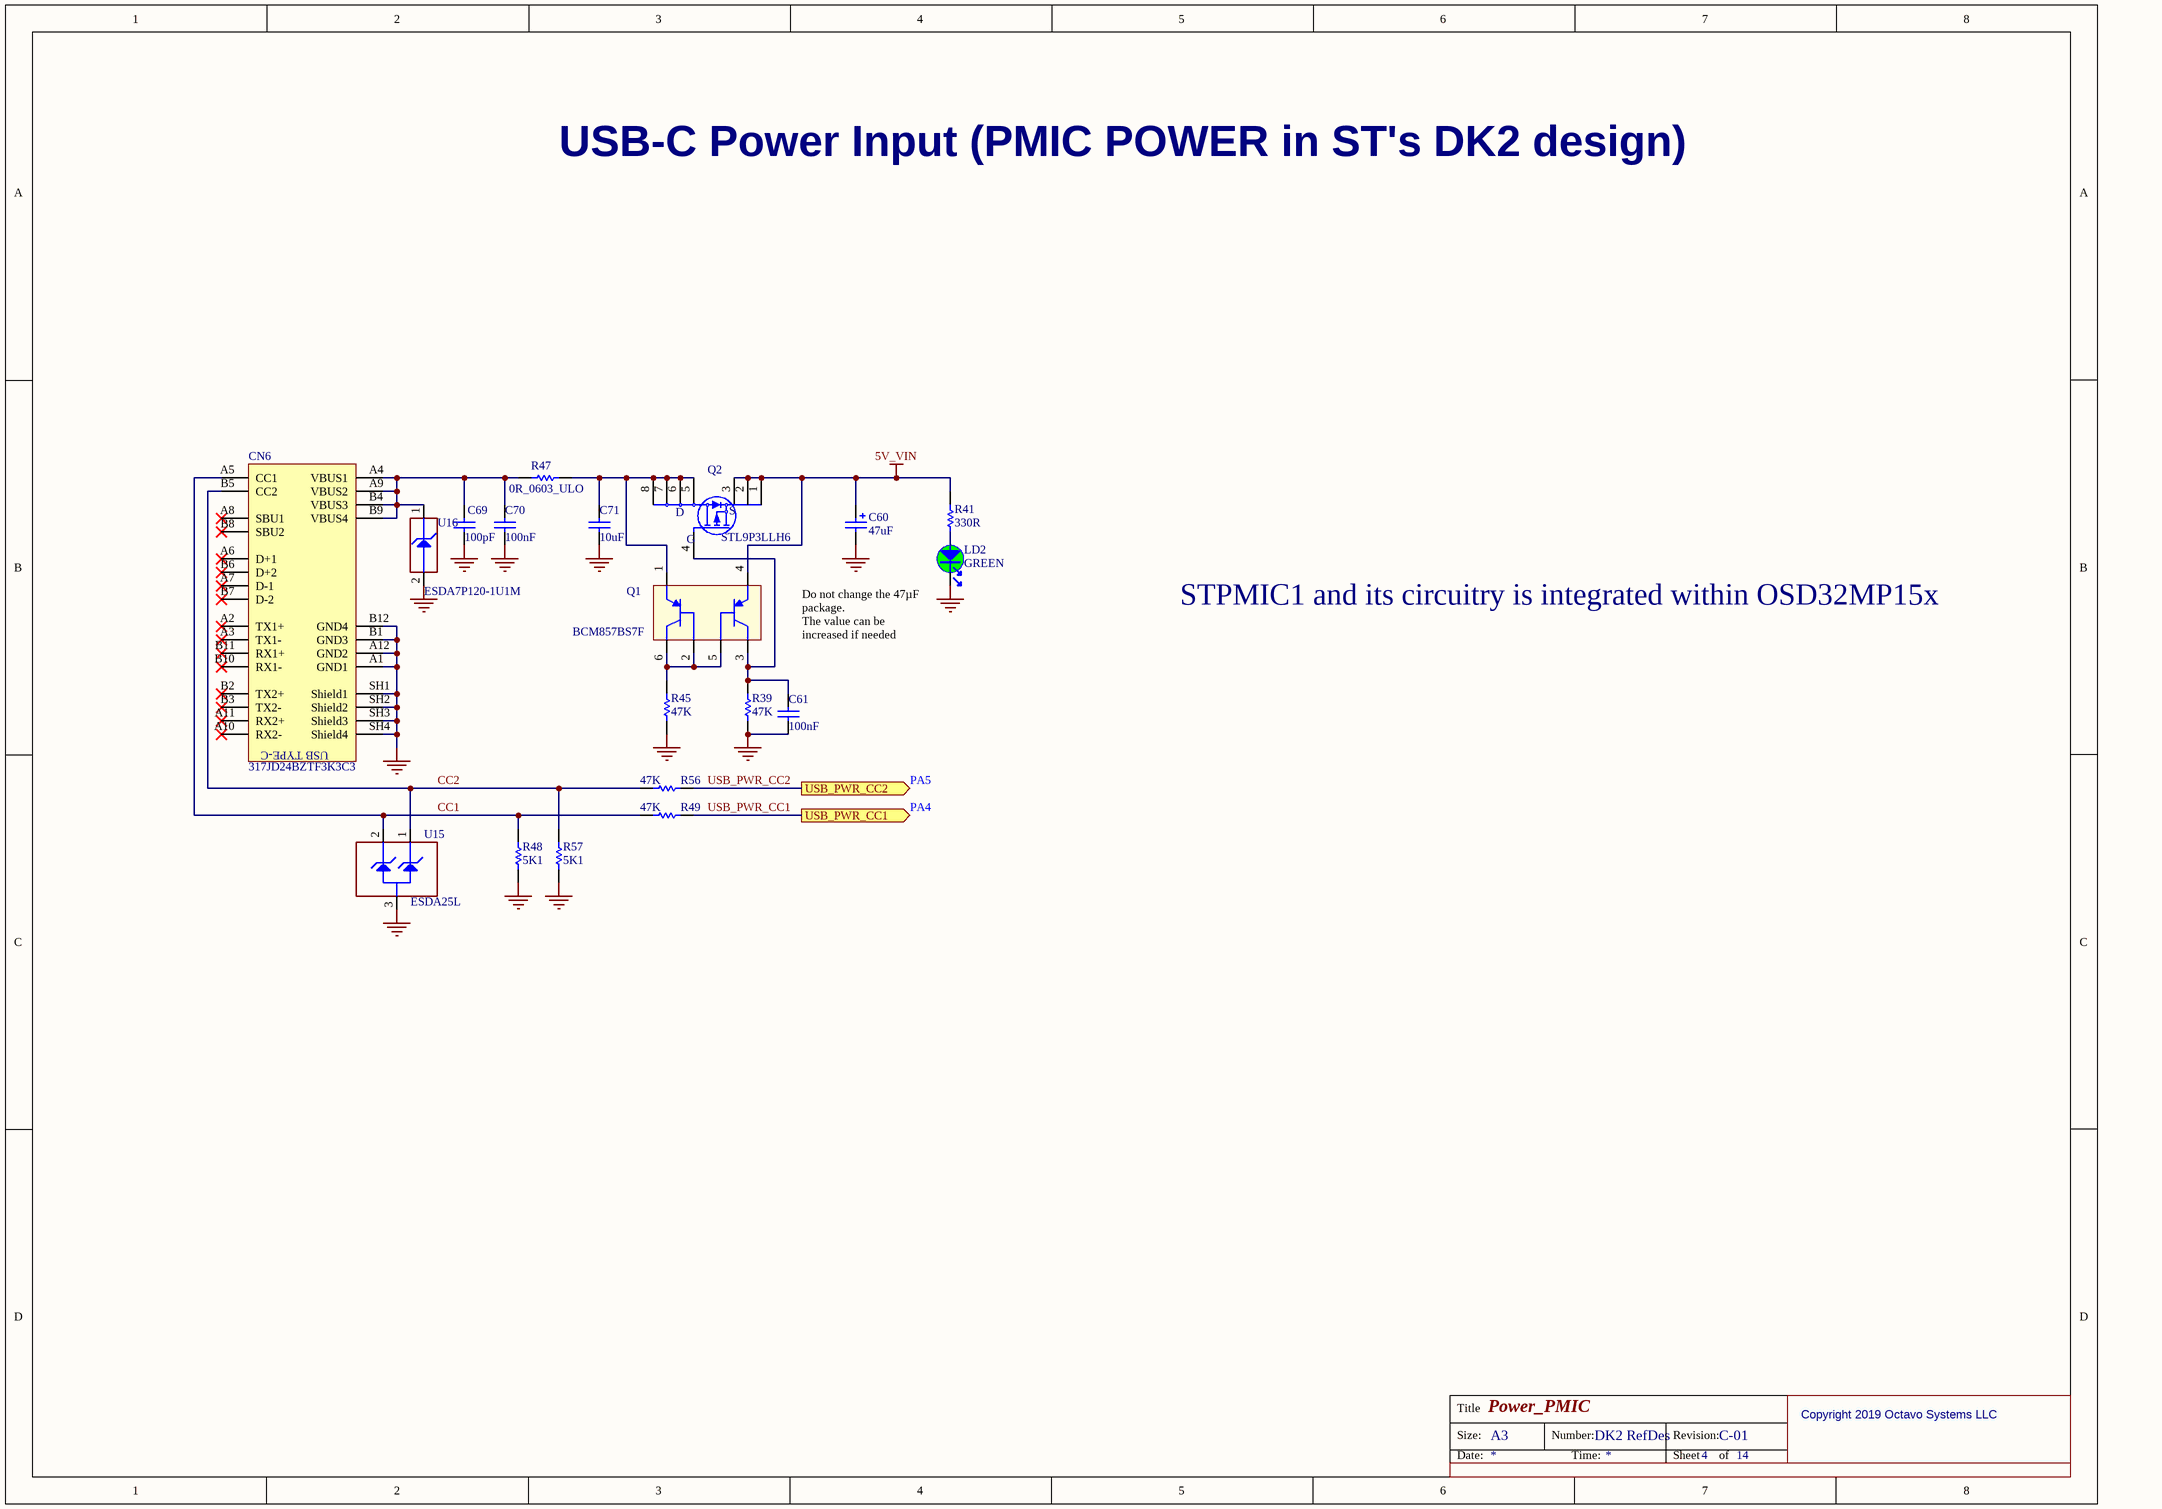
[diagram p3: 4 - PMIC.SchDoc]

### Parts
C60  value 47uF  [CPOL_TAJ-C_2312_H2P6]  (hidden comment: Cap_POL_TANA)
C61  value 100nF  [C0402]
C69  value 100pF  [C0402]  (hidden comment: Capacitor)
C70  value 100nF  [C0402]
C71  value 10uF  [C0805]  (hidden comment: Capacitor)
CN6  value 317JD24BZTF3K3C3  [CON_USB-TYPEC_COXOC_317JD24BZTF3K3C3]
LD2  value GREEN  [LED_0603_GREEN]
Q1  value BCM857BS7F  [DIO_SOT363]  (hidden comment: BCM857BS)
Q2  value STL9P3LLH6  [MOS_POWERFLAT_3P3X3P3_P065]
R39  value 47K  [R0402]  (hidden comment: Resistor)
R41  value 330R  [R0402]
R45  value 47K  [R0402]  (hidden comment: Resistor)
R47  value 0R_0603_ULO  [R0603]
R48  value 5K1  [R0402]  (hidden comment: Resistor)
R49  value 47K  [R0402]  (hidden comment: Resistor)
R56  value 47K  [R0402]  (hidden comment: Resistor)
R57  value 5K1  [R0402]  (hidden comment: Resistor)
U15  value ESDA25L  [ESD_SOT23]  (hidden comment: New schematic symbol : correction 2 diodes instead of one)
U16  value ESDA7P120-1U1M  [ESD_QFN1610_2N_1K_2A]  (hidden comment: ​Footprint needed DFN105P160X60-2N)

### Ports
USB_PWR_CC1 (out), USB_PWR_CC2 (out)

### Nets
5V_VIN: C60.1 Q1.4(E2) Q2.1(S) Q2.2(S) Q2.3(S) R41.2
GND: C60.2 C61.2 C69.1 C70.2 C71.1 CN6.A1(GND1) CN6.A12(GND2) CN6.B1(GND3) CN6.B12(GND4) CN6.SH1(Shield1) CN6.SH2(Shield2) CN6.SH3(Shield3) CN6.SH4(Shield4) LD2.2 R39.1 R45.1 R48.1 R57.1 U15.3(GND) U16.2(GND)
CC1: CN6.A5(CC1) R48.2 R49.1 U15.2(IO2)
CC2: CN6.B5(CC2) R56.1 R57.2 U15.1(IO1)
USB_PWR_CC1: R49.2 ; port USB_PWR_CC1
USB_PWR_CC2: R56.2 ; port USB_PWR_CC2
NetC61_1: C61.1 Q1.3(C2) Q2.4(G) R39.2
NetC69_2: C69.2 C70.1 CN6.A4(VBUS1) CN6.A9(VBUS2) CN6.B4(VBUS3) CN6.B9(VBUS4) R47.1 U16.1(IO1)
NetC71_2: C71.2 Q1.1(E1) Q2.5(D) Q2.6(D) Q2.7(D) Q2.8(D) R47.2
NetLD2_1: LD2.1 R41.1
NetQ1_2: Q1.2(B1) Q1.5(B2) Q1.6(C1) R45.2

Not connected (* = marked no-connect by the designer): CN6 A2(TX1+)* A3(TX1-)* A6(D+1)* A7(D-1)* A8(SBU1)* A10(RX2-)* A11(RX2+)* B2(TX2+)* B3(TX2-)* B6(D+2)* B7(D-2)* B8(SBU2)* B10(RX1-)* B11(RX1+)*

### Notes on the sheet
- USB-C Power Input (PMIC POWER in ST's DK2 design)
- (near LD2) Do not change the 47µF package.
  The value can be increased if needed
- STPMIC1 and its circuitry is integrated within OSD32MP15x
- PA5
- PA4
- Copyright 2019 Octavo Systems LLC

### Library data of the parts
C60 = MCD-00559: Capacitor, Tantalum, 47uF, 16V, 10%, TypeC; Manufacturer_Part_Number: TAJC476K016RNJ; Manufacturer: AVX; Provided_By: Subcon; Initial_Board_Reference: MB1331
C61 C70 = MCD-00006: Capacitor,100nF,16V,X7R,10%,0402; Manufacturer_Part_Number: CC0402KRX7R7BB104; Manufacturer: YAGEO; Provided_By: Subcon; Initial_Board_Reference: mb1274
C69 = MCD-00205: Capacitor, MLCC, 100pF, 50V, NPO, 5%, 0402, T=0,5mm; Manufacturer_Part_Number: CC0402JRNPO9BN101; Manufacturer: YAGEO; Provided_By: Subcon
C71 = MCD-00014: Capacitor, MLCC, 10uF, 25V, X5R, 10%, 0805, T=0,85mm; Manufacturer_Part_Number: CC0805KRX5R8BB106; Manufacturer: YAGEO; Provided_By: Subcon; Initial_Board_Reference: MB1274
CN6 = MCD-01108: USB tyce C certified receptacle for 1.6mm pcb height; Part_Type: Connector; Manufacturer: CHANT SINCERE (COXOC); ECCN_US: NA; Provided_By: Subcon; Initial_Board_Reference: MB1272
LD2 = MCD-00050: LED, Green, 0603; Part_Type: Display; Manufacturer_Part_Number: 19-213SYGC/S530-E2/TR8; Manufacturer: EVERLIGHT; ECCN_US: EAR99; ECCN_EU: NEC; Provided_By: Subcon; Initial_Board_Reference: mb1274
Q1 = MCD-01120: Transistor 45V Matched Pair PNP small Signal transistor in SOT363; Part_Type: IC; Manufacturer: DIODES_INC; ECCN_US: NA; Provided_By: Subcon; Initial_Board_Reference: MB1272
Q2 = MCD-01126: Power Mosfet, P-channel,VDS -30V,RDS 12mohm typ,ID -9A; Part_Type: IC; Manufacturer: STMICROELECTRONICS; ECCN_US: EAR99; ECCN_EU: NEC; Provided_By: Subcon; Initial_Board_Reference: MB1272
R39 R45 R49 R56 = MCD-00063: as R12 on sheet 3 - Power_MPU
R41 = MCD-00062: Resistor,330R,0402,1%,1/16W; Manufacturer_Part_Number: RC0402FR-07330RL; Manufacturer: YAGEO; Provided_By: Subcon; Initial_Board_Reference: mb1274
R47 = MCD-00181: Resistor,0R,0603,ULO; Manufacturer_Part_Number: PMR03EZPJ000; Manufacturer: ROHM; Provided_By: Subcon
R48 R57 = MCD-00333: Resistor,5K1,0402,1%,1/16W; Manufacturer_Part_Number: RC0402FR-075K1L; Manufacturer: YAGEO; Provided_By: Subcon; Initial_Board_Reference: MB1272
U15 = MCD-01125: DUAL TRANSIL ARRAY FOR ESD PROTECTION; Part_Type: Diode; Manufacturer: STMICROELECTRONICS; ECCN_US: EAR99; ECCN_EU: NEC; Provided_By: Subcon; Initial_Board_Reference: MB1272
U16 = MCD-01026: High power transient voltage suppressor; Part_Type: Diode; Manufacturer: STMICROELECTRONICS; ECCN_US: EAR99; ECCN_EU: NEC; Provided_By: STM; Initial_Board_Reference: MB1378

## Sheet 5 - USB_Host_Hub&TypeC_DRP.SchDoc: USB_Host_Hub&TypeC_DRP
size A3; CompanyName: Octavo Systems LLC; Address3: Austin, TX; Address4: USA; DocumentNumber: DK2 RefDes; Revision: C-01; SheetNumber: 5; SheetTotal: 14
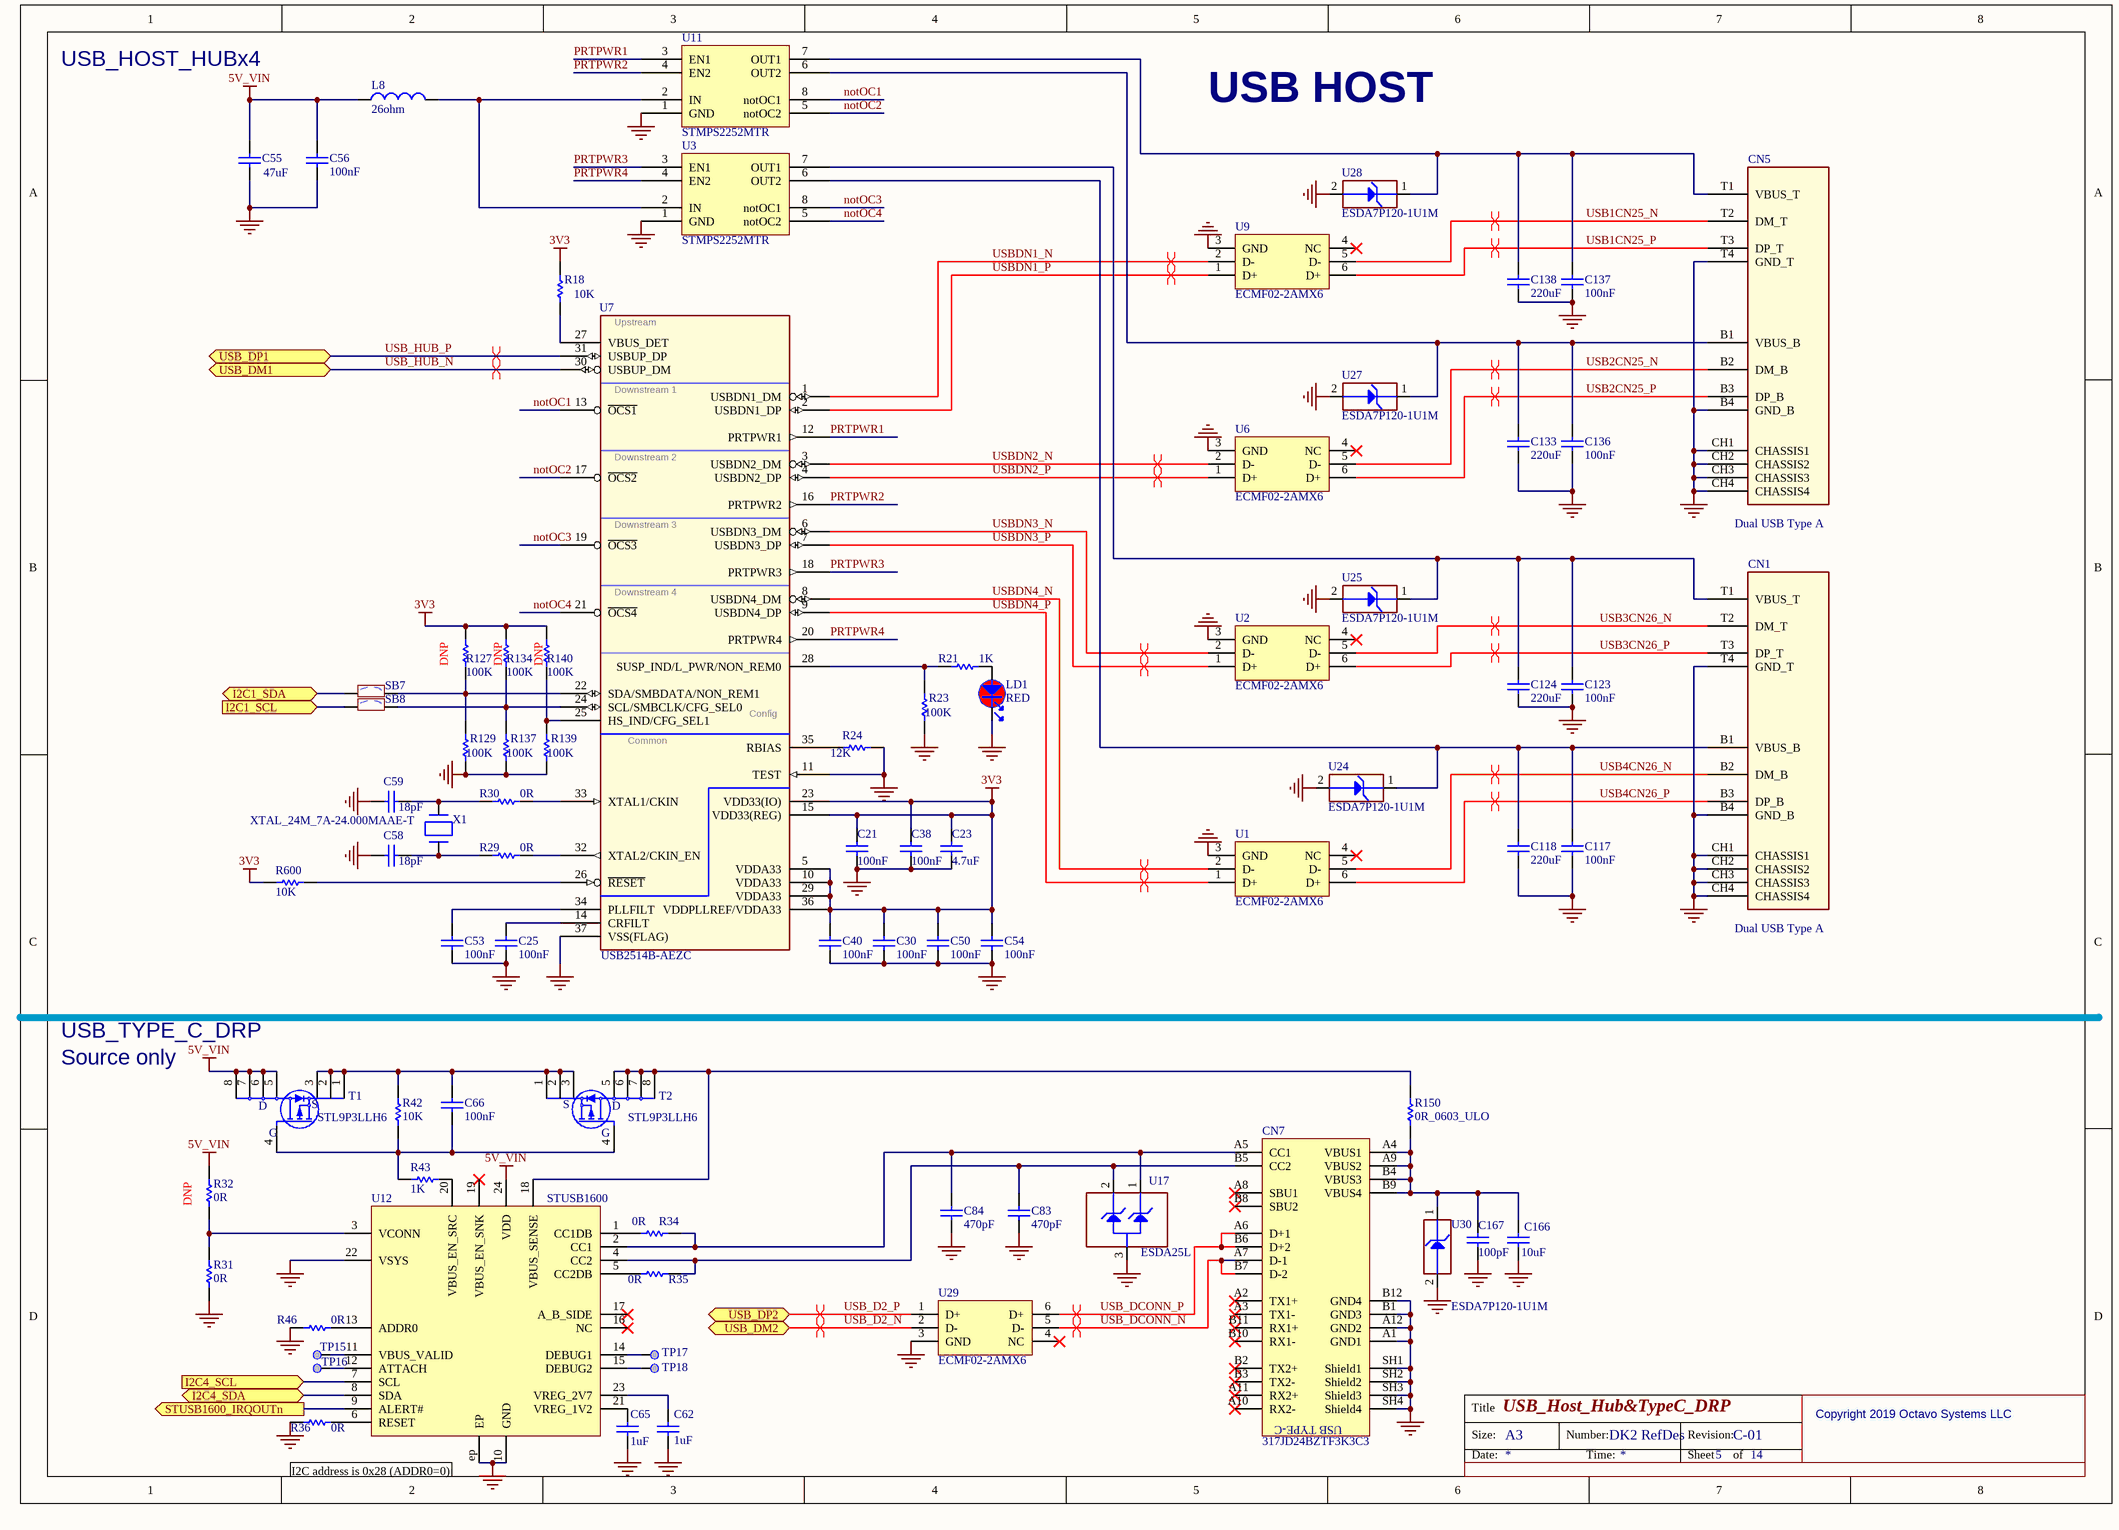
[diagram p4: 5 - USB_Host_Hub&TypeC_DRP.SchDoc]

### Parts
C21  value 100nF  [C0402]  (hidden comment: Capacitor)
C23  value 4.7uF  [C0603]  (hidden comment: Capacitor)
C25  value 100nF  [C0402]  (hidden comment: Capacitor)
C30  value 100nF  [C0402]  (hidden comment: Capacitor)
C38  value 100nF  [C0402]  (hidden comment: Capacitor)
C40  value 100nF  [C0402]  (hidden comment: Capacitor)
C50  value 100nF  [C0402]  (hidden comment: Capacitor)
C53  value 100nF  [C0402]  (hidden comment: Capacitor)
C54  value 100nF  [C0402]  (hidden comment: Capacitor)
C55  value 47uF  [C0805]  (hidden comment: Capacitor)
C56  value 100nF  [C0402]  (hidden comment: Capacitor)
C58  value 18pF  [C0402]  (hidden comment: Capacitor)
C59  value 18pF  [C0402]  (hidden comment: Capacitor)
C62  value 1uF  [C0402]  (hidden comment: Capacitor)
C65  value 1uF  [C0402]  (hidden comment: Capacitor)
C66  value 100nF  [C0402]  (hidden comment: Capacitor)
C83  value 470pF  [C0402]  (hidden comment: Capacitor)
C84  value 470pF  [C0402]  (hidden comment: Capacitor)
C117  value 100nF  [C0402]  (hidden comment: Capacitor)
C118  value 220uF  [C1206_H1P6]  (hidden comment: Capacitor)
C123  value 100nF  [C0402]  (hidden comment: Capacitor)
C124  value 220uF  [C1206_H1P6]  (hidden comment: Capacitor)
C133  value 220uF  [C1206_H1P6]  (hidden comment: Capacitor)
C136  value 100nF  [C0402]  (hidden comment: Capacitor)
C137  value 100nF  [C0402]  (hidden comment: Capacitor)
C138  value 220uF  [C1206_H1P6]  (hidden comment: Capacitor)
C166  value 10uF  [C0805]  (hidden comment: Capacitor)
C167  value 100pF  [C0402]  (hidden comment: Capacitor)
CN1  value Dual USB Type A  [CON_DUAL-USB-TYPE-A_CONEXCON_5600-3081]  (hidden comment: USB_DUAL_TYPEA_5600-3081)
CN5  value Dual USB Type A  [CON_DUAL-USB-TYPE-A_CONEXCON_5600-3081]  (hidden comment: USB_DUAL_TYPEA_5600-3081)
CN7  value 317JD24BZTF3K3C3  [CON_USB-TYPEC_COXOC_317JD24BZTF3K3C3]
L8  value 26ohm  [FIL_0603_H0P65]  (hidden comment: BEAD)
LD1  value RED  [LED_0603_RED]  (hidden comment: LED_red)
R18  value 10K  [R0402]  (hidden comment: Resistor)
R21  value 1K  [R0402]  (hidden comment: Resistor)
R23  value 100K  [R0402]  (hidden comment: Resistor)
R24  value 12K  [R0402]  (hidden comment: Resistor)
R29  value 0R  [R0402]  (hidden comment: Resistor)
R30  value 0R  [R0402]  (hidden comment: Resistor)
R31  value 0R  [R0402]  (hidden comment: Resistor)
R32  value 0R  [R0402]  (hidden comment: Resistor)  (no BOM)
R34  value 0R  [R0402]  (hidden comment: Resistor)
R35  value 0R  [R0402]  (hidden comment: Resistor)
R36  value 0R  [R0402]  (hidden comment: Resistor)
R42  value 10K  [R0402]  (hidden comment: Resistor)
R43  value 1K  [R0402]  (hidden comment: Resistor)
R46  value 0R  [R0402]  (hidden comment: Resistor)
R127  value 100K  [R0402]  (hidden comment: Resistor)  (no BOM)
R129  value 100K  [R0402]  (hidden comment: Resistor)
R134  value 100K  [R0402]  (hidden comment: Resistor)  (no BOM)
R137  value 100K  [R0402]  (hidden comment: Resistor)
R139  value 100K  [R0402]  (hidden comment: Resistor)
R140  value 100K  [R0402]  (hidden comment: Resistor)  (no BOM)
R150  value 0R_0603_ULO  [R0603]  (hidden comment: Resistor)
R600  value 10K  [R0402]  (hidden comment: Resistor)
SB7  SB_OFF  [SOLDER-BRIDGE_R0603-0R]  (value not drawn)
SB8  SB_OFF  [SOLDER-BRIDGE_R0603-0R]  (value not drawn)
T1  value STL9P3LLH6  [MOS_POWERFLAT_3P3X3P3_P065]
T2  value STL9P3LLH6  [MOS_POWERFLAT_3P3X3P3_P065]
TP15  Test Point  [TP_SMD_1MM]  (value not drawn)  (no BOM)
TP16  Test Point  [TP_SMD_1MM]  (value not drawn)  (no BOM)
TP17  Test Point  [TP_SMD_1MM]  (value not drawn)  (no BOM)
TP18  Test Point  [TP_SMD_1MM]  (value not drawn)  (no BOM)
U1  value ECMF02-2AMX6  [ESD_QFN-6L_1P7X1P5_P050]  (hidden comment: ​)
U2  value ECMF02-2AMX6  [ESD_QFN-6L_1P7X1P5_P050]  (hidden comment: ​)
U3  STMPS2252MTR  [ICC_SO8_5X4_P127]
U6  value ECMF02-2AMX6  [ESD_QFN-6L_1P7X1P5_P050]  (hidden comment: ​)
U7  USB2514B-AEZC  [ICC_QFN36-EPAD_6X6_P050]
U9  value ECMF02-2AMX6  [ESD_QFN-6L_1P7X1P5_P050]  (hidden comment: ​)
U11  STMPS2252MTR  [ICC_SO8_5X4_P127]
U12  value STUSB1600  [ICC_QFN24-EPAD_4X4_P050]  (hidden comment: ​Symbol correction needed ?)
U17  value ESDA25L  [ESD_SOT23]  (hidden comment: New schematic symbol : correction 2 diodes instead of one)
U24  value ESDA7P120-1U1M  [ESD_QFN1610_2N_1K_2A]  (hidden comment: ​Footprint needed DFN105P160X60-2N)
U25  value ESDA7P120-1U1M  [ESD_QFN1610_2N_1K_2A]  (hidden comment: ​Footprint needed DFN105P160X60-2N)
U27  value ESDA7P120-1U1M  [ESD_QFN1610_2N_1K_2A]  (hidden comment: ​Footprint needed DFN105P160X60-2N)
U28  value ESDA7P120-1U1M  [ESD_QFN1610_2N_1K_2A]  (hidden comment: ​Footprint needed DFN105P160X60-2N)
U29  value ECMF02-2AMX6  [ESD_QFN-6L_1P7X1P5_P050]  (hidden comment: ​)
U30  value ESDA7P120-1U1M  [ESD_QFN1610_2N_1K_2A]  (hidden comment: ​Footprint needed DFN105P160X60-2N)
X1  XTAL_24M_7A-24.000MAAE-T  [CRY_TXC_7A-SERIES_5X3P2_H1P2_2P]

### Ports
I2C1_SCL (in), I2C1_SDA (bidir), I2C4_SCL (in), I2C4_SDA (bidir), STUSB1600_IRQOUTn (out), USB_DM1 (bidir), USB_DM2 (bidir), USB_DP1 (bidir), USB_DP2 (bidir)

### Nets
3V3: C21.2 C23.2 C30.2 C38.2 C40.2 C50.2 C54.2 R18.2 R127.2 R134.2 R140.2 R600.1 U7.5(VDDA33) U7.10(VDDA33) U7.15(VDD33(REG)) U7.23(VDD33(IO)) U7.29(VDDA33) U7.36(VDDPLLREF/VDDA33)
5V_VIN: C55.2 C56.2 L8.1 R32.2 T1.5(D) T1.6(D) T1.7(D) T1.8(D) U12.24(VDD)
GND: C21.1 C23.1 C25.1 C30.1 C38.1 C40.1 C50.1 C53.1 C54.1 C55.1 C56.1 C58.1 C59.1 C62.1 C65.1 C83.1 C84.1 C117.1 C118.1 C123.1 C124.1 C133.1 C136.1 C137.1 C138.1 C166.1 C167.1 CN1.B4(GND_B) CN1.CH1(CHASSIS1) CN1.CH2(CHASSIS2) CN1.CH3(CHASSIS3) CN1.CH4(CHASSIS4) CN1.T4(GND_T) CN5.B4(GND_B) CN5.CH1(CHASSIS1) CN5.CH2(CHASSIS2) CN5.CH3(CHASSIS3) CN5.CH4(CHASSIS4) CN5.T4(GND_T) CN7.A1(GND1) CN7.A12(GND2) CN7.B1(GND3) CN7.B12(GND4) CN7.SH1(Shield1) CN7.SH2(Shield2) CN7.SH3(Shield3) CN7.SH4(Shield4) LD1.2 R23.1 R24.1 R31.1 R36.1 R46.1 R129.1 R137.1 R139.1 U1.3(GND) U2.3(GND) U3.1(GND) U6.3(GND) U7.11(TEST) U7.37(VSS(FLAG)) U9.3(GND) U11.1(GND) U12.10(GND) U12.22(VSYS) U12.ep(EP) U17.3(GND) U24.2(GND) U25.2(GND) U27.2(GND) U28.2(GND) U29.3(GND) U30.2(GND)
I2C1_SCL: SB8.1 ; port I2C1_SCL
I2C1_SDA: SB7.1 ; port I2C1_SDA
I2C4_SCL: U12.7(SCL) ; port I2C4_SCL
I2C4_SDA: U12.8(SDA) ; port I2C4_SDA
notOC1: U7.13(~{OCS1}) U11.8(notOC1)
notOC2: U7.17(~{OCS2}) U11.5(notOC2)
notOC3: U3.8(notOC1) U7.19(~{OCS3})
notOC4: U3.5(notOC2) U7.21(~{OCS4})
PRTPWR1: U7.12(PRTPWR1) U11.3(EN1)
PRTPWR2: U7.16(PRTPWR2) U11.4(EN2)
PRTPWR3: U3.3(EN1) U7.18(PRTPWR3)
PRTPWR4: U3.4(EN2) U7.20(PRTPWR4)
STUSB1600_IRQOUTn: U12.9(ALERT#) ; port STUSB1600_IRQOUTn
USB1CN25_N: CN5.T2(DM_T) U9.5(D-)
USB1CN25_P: CN5.T3(DP_T) U9.6(D+)
USB2CN25_N: CN5.B2(DM_B) U6.5(D-)
USB2CN25_P: CN5.B3(DP_B) U6.6(D+)
USB3CN26_N: CN1.T2(DM_T) U2.5(D-)
USB3CN26_P: CN1.T3(DP_T) U2.6(D+)
USB4CN26_N: CN1.B2(DM_B) U1.5(D-)
USB4CN26_P: CN1.B3(DP_B) U1.6(D+)
USB_D2_N: U29.2(D-) ; port USB_DM2  [project net USB2_N]
USB_D2_P: U29.1(D+) ; port USB_DP2  [project net USB2_P]
USB_DCONN_N: CN7.A7(D-1) CN7.B7(D-2) U29.5(D-)
USB_DCONN_P: CN7.A6(D+1) CN7.B6(D+2) U29.6(D+)
USB_HUB_N: U7.30(USBUP_DM) ; port USB_DM1  [project net USB1_N]
USB_HUB_P: U7.31(USBUP_DP) ; port USB_DP1  [project net USB1_P]
USBDN1_N: U7.1(USBDN1_DM) U9.2(D-)
USBDN1_P: U7.2(USBDN1_DP) U9.1(D+)
USBDN2_N: U6.2(D-) U7.3(USBDN2_DM)
USBDN2_P: U6.1(D+) U7.4(USBDN2_DP)
USBDN3_N: U2.2(D-) U7.6(USBDN3_DM)
USBDN3_P: U2.1(D+) U7.7(USBDN3_DP)
USBDN4_N: U1.2(D-) U7.8(USBDN4_DM)
USBDN4_P: U1.1(D+) U7.9(USBDN4_DP)
NetC25_2: C25.2 U7.14(CRFILT)
NetC53_2: C53.2 U7.34(PLLFILT)
NetC58_2: C58.2 R29.1 X1.1(X1)
NetC59_2: C59.2 R30.1 X1.2(X2)
NetC62_2: C62.2 U12.23(VREG_2V7)
NetC65_2: C65.2 U12.21(VREG_1V2)
NetC66_1: C66.1 R42.1 R43.1 T1.4(G) T2.4(G)
NetC66_2: C66.2 R42.2 T1.1(S) T1.2(S) T1.3(S) T2.1(S) T2.2(S) T2.3(S)
NetC83_2: C83.2 CN7.B5(CC2) R35.2 U12.4(CC2) U17.2(IO2)
NetC84_2: C84.2 CN7.A5(CC1) R34.2 U12.2(CC1) U17.1(IO1)
NetC117_2: C117.2 C118.2 CN1.B1(VBUS_B) U3.6(OUT2) U24.1(IO1)
NetC123_2: C123.2 C124.2 CN1.T1(VBUS_T) U3.7(OUT1) U25.1(IO1)
NetC133_2: C133.2 C136.2 CN5.B1(VBUS_B) U11.6(OUT2) U27.1(IO1)
NetC137_2: C137.2 C138.2 CN5.T1(VBUS_T) U11.7(OUT1) U28.1(IO1)
NetC166_2: C166.2 C167.2 CN7.A4(VBUS1) CN7.A9(VBUS2) CN7.B4(VBUS3) CN7.B9(VBUS4) R150.1 U30.1(IO1)
NetL8_2: L8.2 U3.2(IN) U11.2(IN)
NetLD1_1: LD1.1 R21.1
NetR18_1: R18.1 U7.27(VBUS_DET)
NetR21_2: R21.2 R23.2 U7.28(SUSP_IND/L_PWR/NON_REM0)
NetR24_2: R24.2 U7.35(RBIAS)
NetR29_2: R29.2 U7.32(XTAL2/CKIN_EN)
NetR30_2: R30.2 U7.33(XTAL1/CKIN)
NetR31_2: R31.2 R32.1 U12.3(VCONN)
NetR34_1: R34.1 U12.1(CC1DB)
NetR35_1: R35.1 U12.5(CC2DB)
NetR36_2: R36.2 U12.6(RESET)
NetR43_2: R43.2 U12.20(VBUS_EN_SRC)
NetR46_2: R46.2 U12.13(ADDR0)
NetR127_1: R127.1 R129.2 SB7.2 U7.22(SDA/SMBDATA/NON_REM1)
NetR134_1: R134.1 R137.2 SB8.2 U7.24(SCL/SMBCLK/CFG_SEL0)
NetR139_2: R139.2 R140.1 U7.25(HS_IND/CFG_SEL1)
NetR150_2: R150.2 T2.5(D) T2.6(D) T2.7(D) T2.8(D) U12.18(VBUS_SENSE)
NetR600_2: R600.2 U7.26(~{RESET})
NetTP15_1: TP15.1 U12.11(VBUS_VALID)
NetTP16_1: TP16.1 U12.12(ATTACH)
NetTP17_1: TP17.1 U12.14(DEBUG1)
NetTP18_1: TP18.1 U12.15(DEBUG2)

Not connected (* = marked no-connect by the designer): CN7 A2(TX1+)* A3(TX1-)* A8(SBU1)* A10(RX2-)* A11(RX2+)* B2(TX2+)* B3(TX2-)* B8(SBU2)* B10(RX1-)* B11(RX1+)*; U1 4(NC)*; U2 4(NC)*; U6 4(NC)*; U9 4(NC)*; U12 16(NC)* 17(A_B_SIDE)* 19(VBUS_EN_SNK)*; U29 4(NC)*

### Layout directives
differential pair: USB1_N, USB1_P, USB1CN25_N, USB1CN25_P, USB2_N, USB2_P, USB2CN25_N, USB2CN25_P, USB3CN26_N, USB3CN26_P, USB4CN26_N, USB4CN26_P, USB_DCONN_N, USB_DCONN_P, USBDN1_N, USBDN1_P, USBDN2_N, USBDN2_P, USBDN3_N, USBDN3_P, USBDN4_N, USBDN4_P

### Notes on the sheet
- USB_HOST_HUBx4
- USB HOST
- (near R127) DNP
- (near R134) DNP
- (near R140) DNP
- USB_TYPE_C_DRP
- Source only
- (near R32) DNP
- Copyright 2019 Octavo Systems LLC
- I2C address is 0x28 (ADDR0=0)

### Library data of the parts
C21 C25 C30 C38 C40 C50 C53 C54 C56 C66 C117 C123 C136 C137 = MCD-00102: Capacitor, MLCC, 100nF, 16V, X7R, 10%, 0402, T=0,5mm; Manufacturer_Part_Number: CC0402KRX7R7BB104; Manufacturer: YAGEO; Provided_By: Subcon; Initial_Board_Reference: MB1262
C23 = MCD-00009: Capacitor, MLCC, 4.7uF, 16V, X5R, 10%, 0603, T=0.8mm; Manufacturer_Part_Number: CC0603KRX5R7BB475; Manufacturer: YAGEO; Provided_By: subcon; Initial_Board_Reference: MB1274
C55 = MCD-00204: Capacitor, MLCC, 47uF, 10V, X5R, 20%, 0805, T=1,25mm; Manufacturer_Part_Number: GRM21BR61A476ME15K; Manufacturer: MURATA; Provided_By: Subcon; ECCN_US: EAR99; ECCN_EU: NEC
C58 C59 = MCD-00201: Capacitor, MLCC, 18pF, 50V, NPO, 5%, 0402, T=0,5mm; Manufacturer_Part_Number: CC0402JRNPO9BN180; Manufacturer: YAGEO; Provided_By: Subcon
C62 C65 = MCD-00095: Capacitor, MLCC, 1uF, 6V3, X5R, 10%, 0402, T=0,5mm; Manufacturer_Part_Number: GRM155R60J105KE19; Manufacturer: MURATA; ECCN_US: EAR99; ECCN_EU: NEC; Provided_By: Subcon; Initial_Board_Reference: MB1262
C83 C84 = MCD-00724: Capacitor, MLCC, 470pF, 50V, NPO, 5%, 0402, T=0,5mm; Manufacturer_Part_Number: CC0402JRNPO9BN471; Manufacturer: YAGEO; Provided_By: Subcon; Initial_Board_Reference: MB1271
C118 C124 C133 C138 = MCD-00104: Capacitor, MLCC, 220uF, 6V3, X5R, 20%, 1206, T=1,6mm; Manufacturer_Part_Number: GRM31CR60J227ME11; Manufacturer: MURATA; ECCN_US: EAR99; ECCN_EU: NEC; Provided_By: Subcon; Initial_Board_Reference: MB1262
C166 = MCD-00014: as C71 on sheet 4 - PMIC
C167 = MCD-00205: as C69 on sheet 4 - PMIC
CN1 CN5 = MCD-00109: USB-Receptacle,Dual-Type-A, RA, TH, Height 15.5mm; Manufacturer: CONEXCON; Part_Type: Connector; Provided_By: Subcon; Initial_Board_Reference: MB1262
CN7 = MCD-01108: as CN6 on sheet 4 - PMIC
L8 = MCD-00305: Bead,26R at 100Mhz,6A,0603; Manufacturer_Part_Number: BLM18KG260TN1; Manufacturer: MURATA; Part_Type: Inductor; Provided_By: Subcon; Initial_Board_Reference: MB1272
LD1 = MCD-00049: LED, Red, 0603; Manufacturer_Part_Number: 19-213-R6C-AP1Q2B/3T; Manufacturer: EVERLIGHT; Part_Type: Display; ECCN_US: EAR99; ECCN_EU: NEC; Provided_By: Subcon; Initial_Board_Reference: MB1274
R18 R42 R600 = MCD-00053: as R40 on sheet 2 - OSD32MP157C_18x18
R21 R43 = MCD-00061: Resistor,1K,0402,1%,1/16W; Manufacturer_Part_Number: RC0402FR-071KL; Manufacturer: YAGEO; Provided_By: Subcon; Initial_Board_Reference: MB1274
R23 R127 R129 R134 R137 R139 R140 = MCD-00059: Resistor,100K,0402,1%,1/16W; Manufacturer_Part_Number: RC0402FR-07100KL; Manufacturer: YAGEO; Alternate_Manufacturer_Part_Number: RT0402FRE07100KL; Provided_By: Subcon; Initial_Board_Reference: MB1274
R24 = MCD-00187: Resistor,12K,0402,1%,1/16W; Manufacturer_Part_Number: RC0402FR-0712KL; Manufacturer: YAGEO; Provided_By: Subcon
R29-R32 R34-R36 R46 = MCD-00052: as R78 on sheet 3 - Power_MPU
R150 = MCD-00181: as R47 on sheet 4 - PMIC
SB7 SB8 = MCD-00072: Solder Bridge OFF; Part_Type: Mechanical; Initial_Board_Reference: MB1274
T1 T2 = MCD-01126: as Q2 on sheet 4 - PMIC
TP15-TP18 = MCD-00074: as TP1 on sheet 2 - OSD32MP157C_18x18
U1 U2 U6 U9 U29 = MCD-00649: Common mode filter with ESD protection for USB 2.0 interface; Part_Type: Diode; Manufacturer: STMICROELECTRONICS; ECCN_US: EAR99; ECCN_EU: NEC; Provided_By: Subcon; Initial_Board_Reference: MB1248
U3 U11 = MCD-00123: IC,Dual-Channel-Power-Switch,500mA,100mR,SO8; Manufacturer: STMICROELECTRONICS; ECCN_US: EAR99; ECCN_EU: NEC; Provided_By: Subcon; Initial_Board_Reference: MB1262
U7 = MCD-00145: USB HUB 2,0 Controller; Manufacturer: MICROCHIP; Part_Type: IC; ECCN_US: EAR99; ECCN_EU: NEC; Provided_By: Subcon; Initial_Board_Reference: MB1262
U12 = MCD-00676: USB Type-C controller with VCONN switch; Part_Type: IC; Manufacturer: STMICROELECTRONICS; Provided_By: Subcon; Initial_Board_Reference: MB1272
U17 = MCD-01125: as U15 on sheet 4 - PMIC
U24 U25 U27 U28 U30 = MCD-01026: as U16 on sheet 4 - PMIC
X1 = MCD-00140: Crystal, 24.000MHz, 30ppm, 18pF, 7A-24.000MAAE-T; Manufacturer: TXC; Part_Type: Crystal_Osc; Provided_By: Subcon; Initial_Board_Reference: MB1262

## Sheet 6 - AUDIO.SchDoc: AUDIO
size A3; Author: CR; CompanyName: Octavo Systems LLC; Address2: Austin,TX; Address3: USA; DocumentNumber: DK2 RefDes; Revision: C-01; SheetNumber: 6; SheetTotal: 14
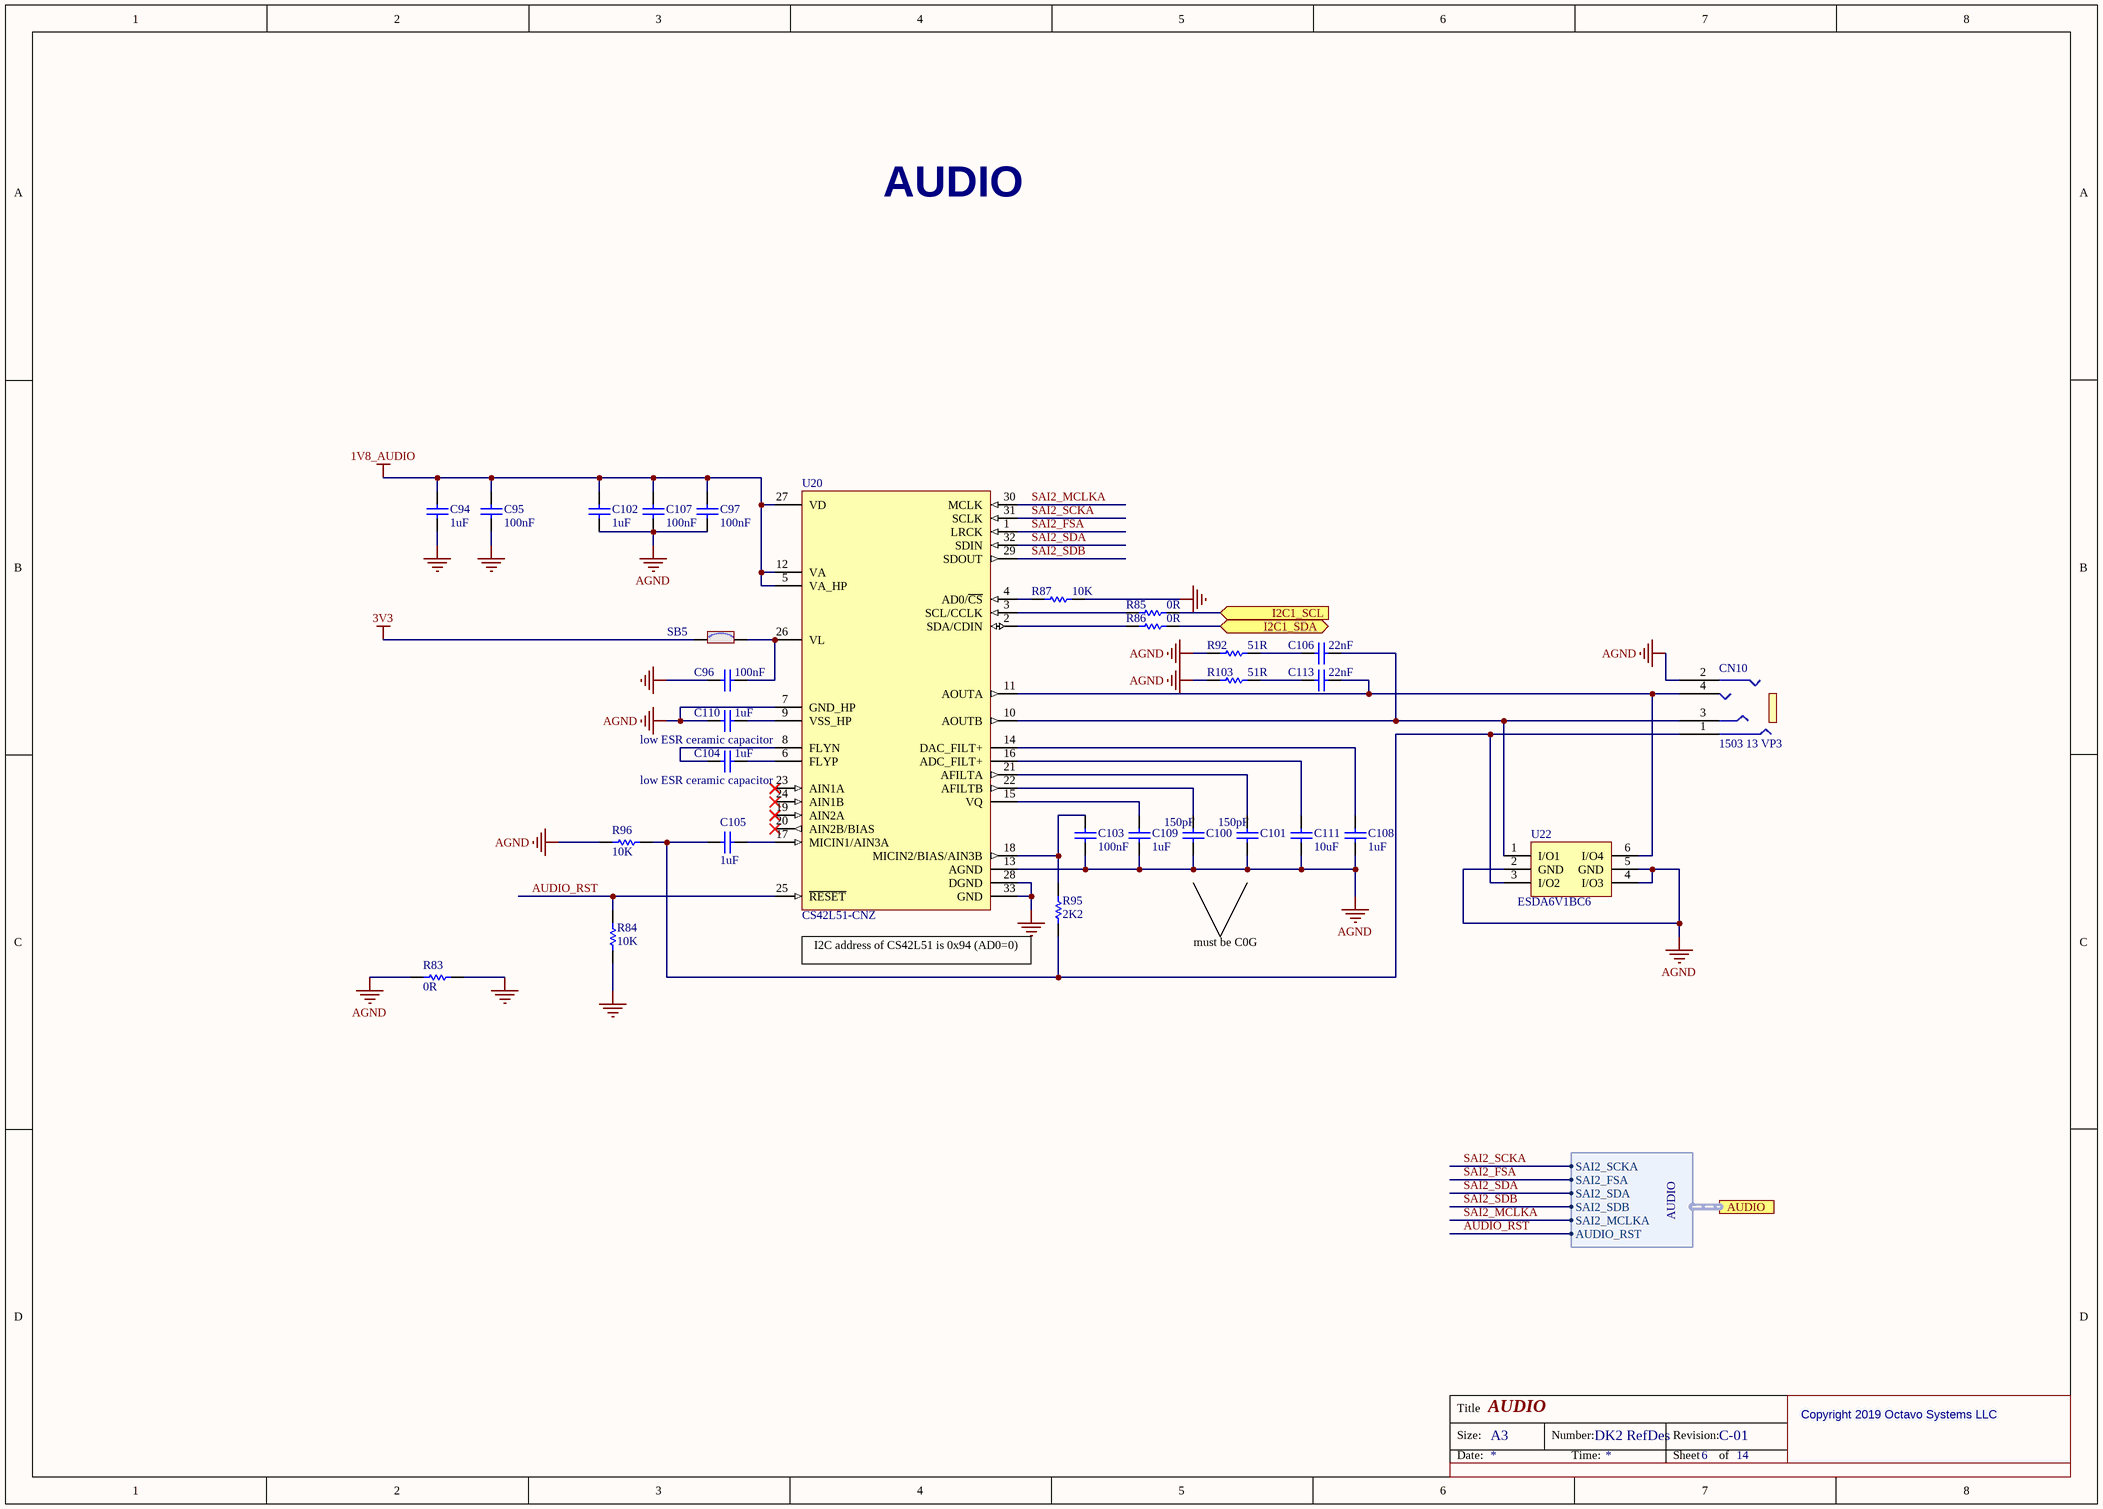
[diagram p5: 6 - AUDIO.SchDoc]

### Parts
C94  value 1uF  [C0402]
C95  value 100nF  [C0402]
C96  value 100nF  [C0402]
C97  value 100nF  [C0402]
C100  value 150pF  [C0603]
C101  value 150pF  [C0603]
C102  value 1uF  [C0402]
C103  value 100nF  [C0402]
C104  value 1uF  [C0603]
C105  value 1uF  [C0402]
C106  value 22nF  [C0402]
C107  value 100nF  [C0402]
C108  value 1uF  [C0402]
C109  value 1uF  [C0402]
C110  value 1uF  [C0603]
C111  value 10uF  [C0603]
C113  value 22nF  [C0402]
CN10  value 1503 13 VP3  [CON_JACK-3P5-SMT_LUMBERG_1503-13-VP3]
R83  value 0R  [R0603]
R84  value 10K  [R0402]
R85  value 0R  [R0402]
R86  value 0R  [R0402]
R87  value 10K  [R0402]
R92  value 51R  [R0402]
R95  value 2K2  [R0402]
R96  value 10K  [R0402]
R103  value 51R  [R0402]
SB5  (no value)  [SOLDER-BRIDGE_R0603-0R]
U20  value CS42L51-CNZ  [ICC_QFN32-EPAD_5X5_P050]
U22  value ESDA6V1BC6  [ESD_SOT23-6L]

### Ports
AUDIO (harness AUDIO), I2C1_SCL (in), I2C1_SDA (bidir)

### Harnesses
AUDIO: SAI2_SCKA, SAI2_FSA, SAI2_SDA, SAI2_SDB, SAI2_MCLKA, AUDIO_RST

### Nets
1V8_AUDIO: C94.2 C95.2 C97.2 C102.2 C107.2 U20.5(VA_HP) U20.12(VA) U20.27(VD)
3V3: SB5.1
AGND: C97.1 C100.1 C101.1 C102.1 C103.1 C107.1 C108.1 C109.1 C110.1 C111.1 CN10.2 R83.1 R92.1 R96.1 R103.1 U20.7(GND_HP) U20.13(AGND) U22.2(GND) U22.4(I/O3) U22.5(GND)
GND: C94.1 C95.1 C96.2 R83.2 R84.1 R87.2 U20.28(DGND) U20.33(GND)
AUDIO_RST: R84.2 U20.25(~{RESET}) ; port AUDIO.AUDIO_RST
I2C1_SCL: R85.2 ; port I2C1_SCL
I2C1_SDA: R86.2 ; port I2C1_SDA
SAI2_FSA: U20.1(LRCK) ; port AUDIO.SAI2_FSA
SAI2_MCLKA: U20.30(MCLK) ; port AUDIO.SAI2_MCLKA
SAI2_SCKA: U20.31(SCLK) ; port AUDIO.SAI2_SCKA
SAI2_SDA: U20.32(SDIN) ; port AUDIO.SAI2_SDA
SAI2_SDB: U20.29(SDOUT) ; port AUDIO.SAI2_SDB
NetC96_1: C96.1 SB5.2 U20.26(VL)
NetC100_2: C100.2 U20.22(AFILTB)
NetC101_2: C101.2 U20.21(AFILTA)
NetC103_2: C103.2 R95.2 U20.18(MICIN2/BIAS/AIN3B)
NetC104_1: C104.1 U20.8(FLYN)
NetC104_2: C104.2 U20.6(FLYP)
NetC105_1: C105.1 CN10.1 R95.1 R96.2 U22.3(I/O2)
NetC105_2: C105.2 U20.17(MICIN1/AIN3A)
NetC106_1: C106.1 R92.2
NetC106_2: C106.2 CN10.3 U20.10(AOUTB) U22.1(I/O1)
NetC108_2: C108.2 U20.14(DAC_FILT+)
NetC109_2: C109.2 U20.15(VQ)
NetC110_2: C110.2 U20.9(VSS_HP)
NetC111_2: C111.2 U20.16(ADC_FILT+)
NetC113_1: C113.1 R103.2
NetC113_2: C113.2 CN10.4 U20.11(AOUTA) U22.6(I/O4)
NetR85_1: R85.1 U20.3(SCL/CCLK)
NetR86_1: R86.1 U20.2(SDA/CDIN)
NetR87_1: R87.1 U20.4(AD0/~{CS})

Not connected (* = marked no-connect by the designer): U20 19(AIN2A)* 20(AIN2B/BIAS)* 23(AIN1A)* 24(AIN1B)*

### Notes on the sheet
- AUDIO
- low ESR ceramic capacitor
- I2C address of CS42L51 is 0x94 (AD0=0)
- must be C0G
- Copyright 2019 Octavo Systems LLC

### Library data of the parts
C94 C102 C105 C108 C109 = MCD-00095: Capacitor,1uF,6V3,X5R,10%,0402; Manufacturer_Part_Number: GRM155R60J105KE19; Manufacturer: MURATA; ECCN_US: EAR99; ECCN_EU: NEC; Provided_By: Subcon; Initial_Board_Reference: mb1262
C95-C97 C103 C107 = MCD-00006: as C61 on sheet 4 - PMIC
C100 C101 = MCD-00304: Capacitor,150pF,50V,COG,5%,0603; Manufacturer_Part_Number: CC0603JRNPO9BN151; Manufacturer: YAGEO; Provided_By: Subcon; Initial_Board_Reference: mb1263
C104 C110 = MCD-00010: Capacitor,1uF,16V,X5R,10%,0603; Manufacturer_Part_Number: CC0603KRX5R7BB105; Manufacturer: YAGEO; Provided_By: Subcon; Initial_Board_Reference: mb1274
C106 C113 = MCD-00202: Capacitor,22nF,16V,X7R,10%,0402; Manufacturer_Part_Number: CC0402KRX7R7BB223; Manufacturer: YAGEO; Provided_By: Subcon
C111 = MCD-00098: Capacitor,10uF,6V3,X5R,10%,0603; Manufacturer_Part_Number: CC0603KRX5R5BB106; Manufacturer: YAGEO; Provided_By: Subcon; Initial_Board_Reference: mb1262
CN10 = MCD-00270: Connector Jack socket Stereo 3.5mm, 4 pins, RA, SMT, Black; Manufacturer: LUMBERG; Alternate_Manufacturer: FARNELL; Alternate_Manufacturer_Part_Number: 1368640; Provided_By: Subcon; Initial_Board_Reference: MB1272
R83 = MCD-00056: Resistor,0R,0603,5%,1/10W; Manufacturer_Part_Number: RC0603JR-070RL; Manufacturer: YAGEO; Provided_By: subcon; Initial_Board_Reference: mb1274
R84 R87 R96 = MCD-00053: Resistor,10K,0402,1%,1/16W; Manufacturer_Part_Number: RC0402FR-0710KL; Manufacturer: YAGEO; Provided_By: subcon; Initial_Board_Reference: mb1274
R85 R86 = MCD-00052: as R71 on sheet 2 - OSD32MP157C_18x18
R92 R103 = MCD-00485: Resistor,51R,0402,1%,1/16W; Manufacturer_Part_Number: RC0402FR-0751RL; Manufacturer: YAGEO; Provided_By: Subcon
R95 = MCD-00057: Resistor,2K2,0402,1%,1/16W; Manufacturer_Part_Number: RC0402FR-072K2L; Manufacturer: YAGEO; Provided_By: Subcon; Initial_Board_Reference: mb1274
SB5 = MCD-00071: as SB1 on sheet 2 - OSD32MP157C_18x18
U20 = MCD-00265: Low-Power, Stereo Codec with Headphone Amp; Manufacturer: CIRRUS LOGIC; Part_Type: IC; Provided_By: Subcon; ECCN_US: EAR99; ECCN_EU: NEC; Initial_Board_Reference: MB1272
U22 = MCD-00247: Quad Bidir ESD protection; Manufacturer: STMICROELECTRONICS; Part_Type: IC; Provided_By: Subcon; ECCN_US: EAR99; ECCN_EU: NEC; Initial_Board_Reference: MB1311

## Sheet 7 - DSI_LCD.SchDoc: DSI_LCD_connector
size A3; Date: 29-DEC-2018; Author: A.B; DrawnBy: CR; Address2: Austin,TX; Address3: USA; DocumentNumber: DK2 RefDes; Revision: C-01; SheetNumber: 7; SheetTotal: 14; Project: STM32MP15-DISCO PI
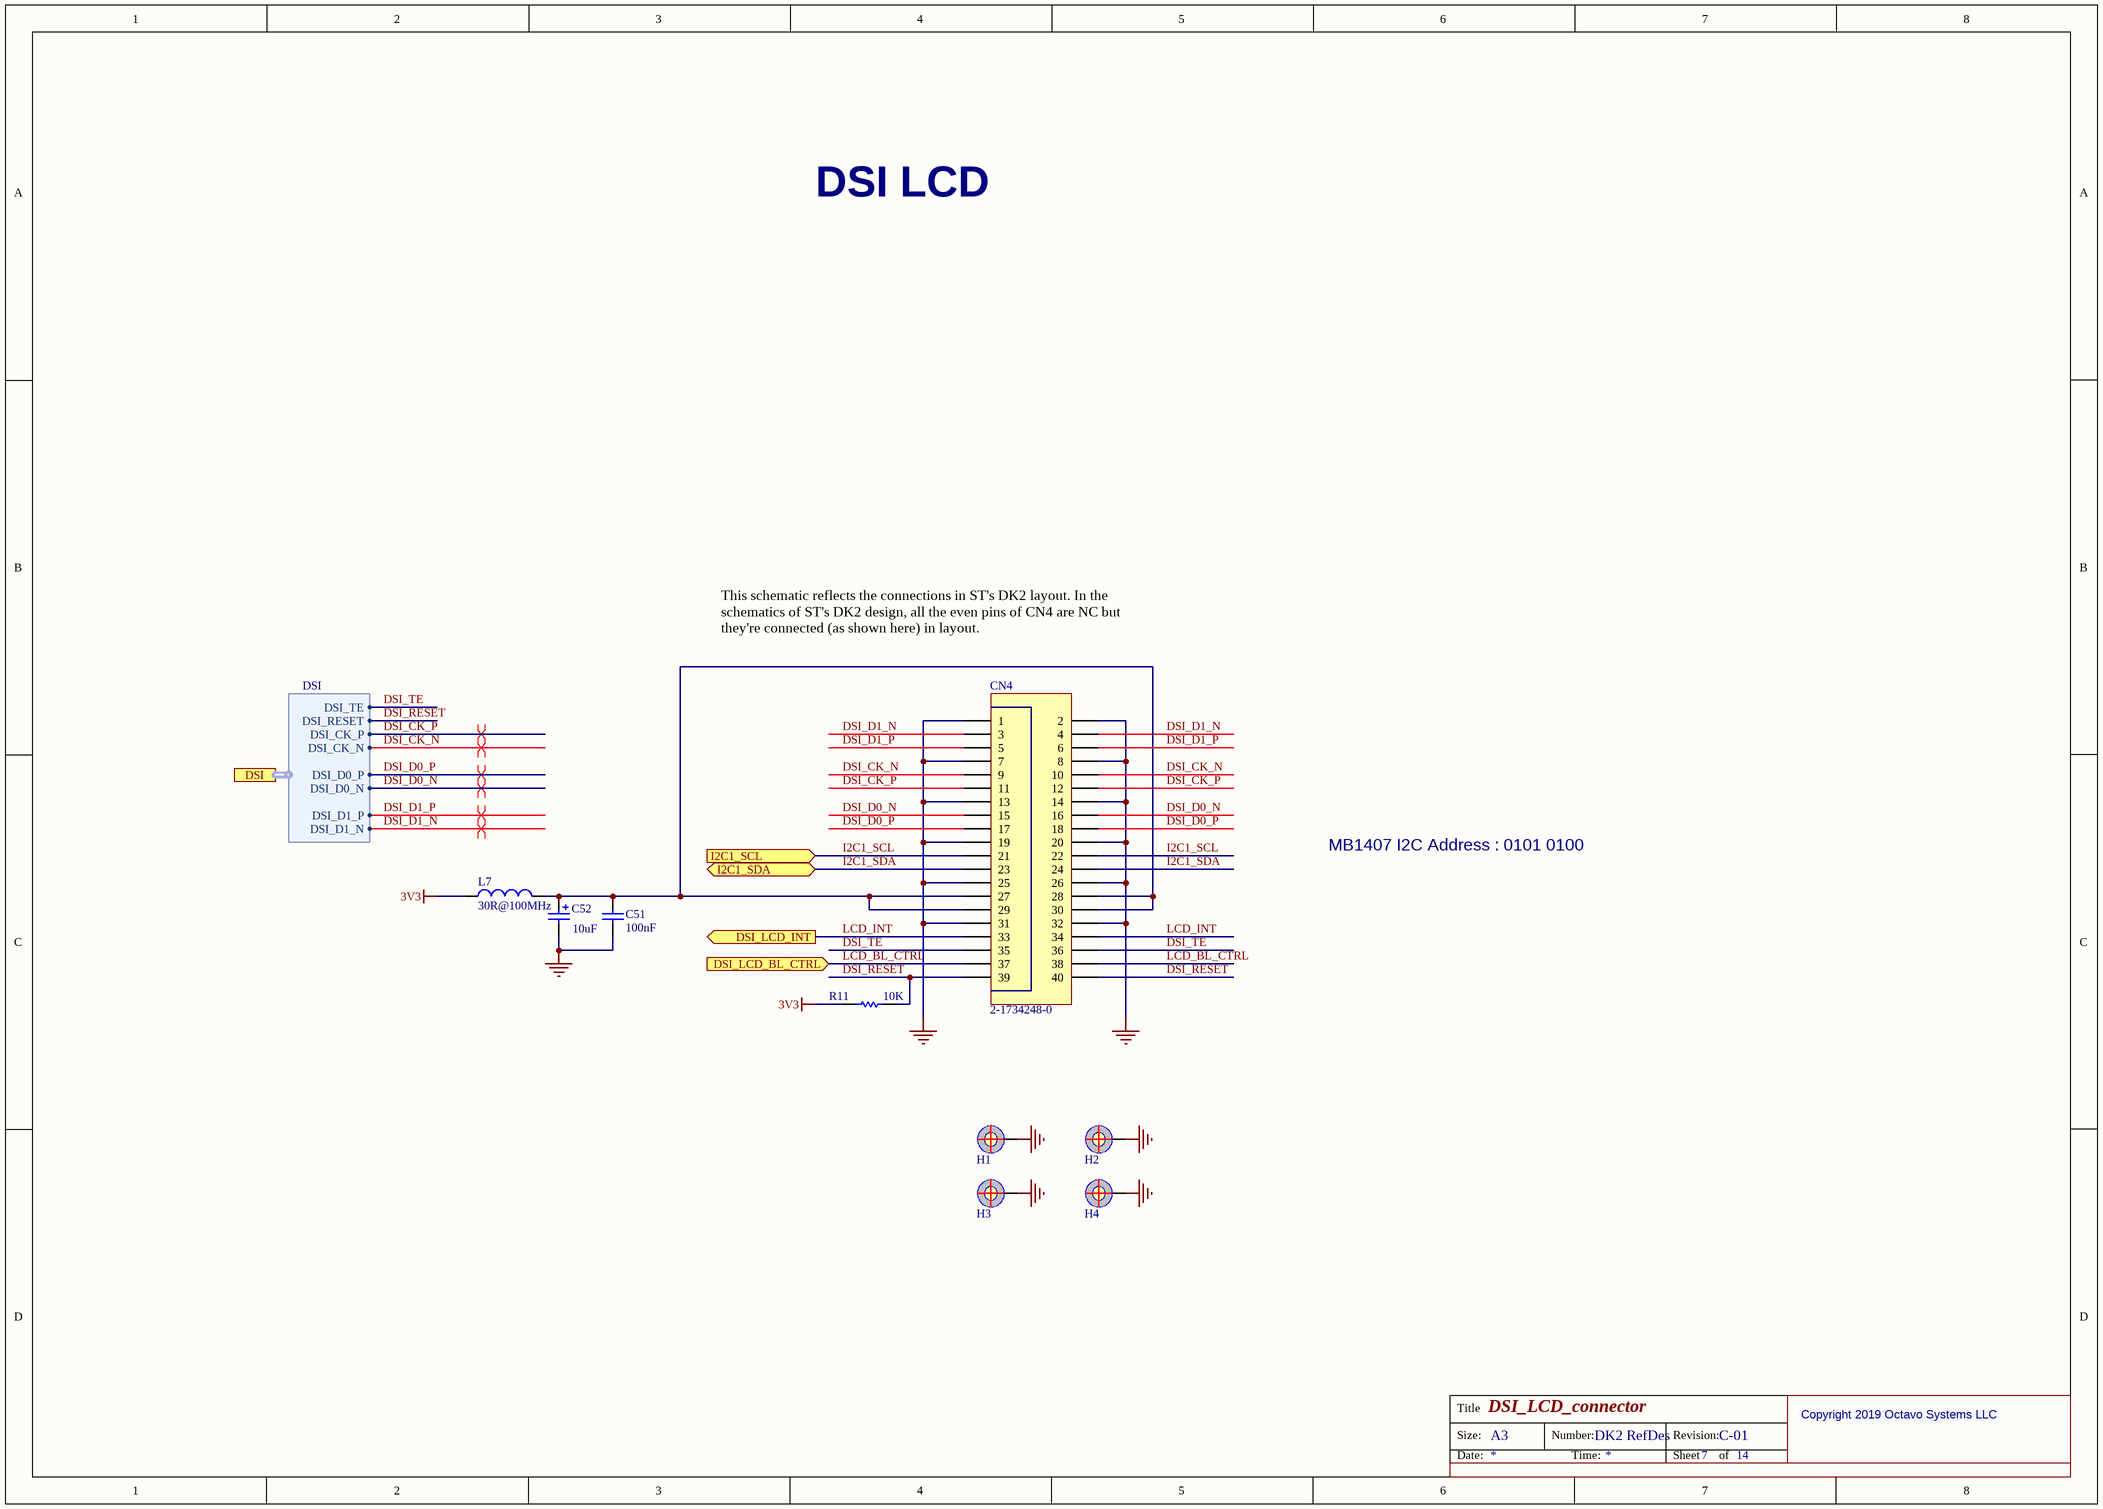
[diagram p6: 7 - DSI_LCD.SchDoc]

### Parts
C51  value 100nF  [C0402]
C52  value 10uF  [CPOL_TAJ-A_1206_H180]
CN4  value 2-1734248-0  [CON_TE-CONNECTIVITY_2-1734248-0]
H1  (no value)  [PTH_M1261-3005-N_3P5X6_M3_H14]  (no BOM)
H2  (no value)  [PTH_M1261-3005-N_3P5X6_M3_H14]  (no BOM)
H3  (no value)  [PTH_M1261-3005-N_3P5X6_M3_H14]  (no BOM)
H4  (no value)  [PTH_M1261-3005-N_3P5X6_M3_H14]  (no BOM)
L7  value 30R@100MHz  [L0603]  (hidden comment: BEAD)
R11  value 10K  [R0402]

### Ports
DSI (harness DSI), DSI_LCD_BL_CTRL (in), DSI_LCD_INT (out), I2C1_SCL (in), I2C1_SDA (bidir)

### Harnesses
DSI: DSI_CK_P, DSI_CK_N, DSI_D0_P, DSI_D0_N, DSI_D1_P, DSI_D1_N, DSI_TE, DSI_RESET

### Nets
3V3: L7.1 R11.1
GND: C51.1 C52.2 CN4.1 CN4.2 CN4.7 CN4.8 CN4.13 CN4.14 CN4.19 CN4.20 CN4.25 CN4.26 CN4.31 CN4.32 H1.1 H2.1 H3.1 H4.1
DSI_CK_N: CN4.9 CN4.10 ; port DSI.DSI_CK_N
DSI_CK_P: CN4.11 CN4.12 ; port DSI.DSI_CK_P
DSI_D0_N: CN4.15 CN4.16 ; port DSI.DSI_D0_N
DSI_D0_P: CN4.17 CN4.18 ; port DSI.DSI_D0_P
DSI_D1_N: CN4.3 CN4.4 ; port DSI.DSI_D1_N
DSI_D1_P: CN4.5 CN4.6 ; port DSI.DSI_D1_P
DSI_RESET: CN4.39 CN4.40 R11.2 ; port DSI.DSI_RESET
DSI_TE: CN4.35 CN4.36 ; port DSI.DSI_TE
I2C1_SCL: CN4.21 CN4.22 ; port I2C1_SCL
I2C1_SDA: CN4.23 CN4.24 ; port I2C1_SDA
LCD_BL_CTRL: CN4.37 CN4.38 ; port DSI_LCD_BL_CTRL  [project net DSI_LCD_BL_CTRL]
LCD_INT: CN4.33 CN4.34 ; port DSI_LCD_INT  [project net DSI_LCD_INT]
NetC51_2: C51.2 C52.1 CN4.27 CN4.28 CN4.29 CN4.30 L7.2

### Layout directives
differential pair: DSI_CK_N, DSI_CK_P, DSI_D0_N, DSI_D0_P, DSI_D1_N, DSI_D1_P

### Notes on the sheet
- DSI LCD
- This schematic reflects the connections in ST's DK2 layout. In the schematics of ST's DK2 design, all the even pins of CN4 are NC but they're connected (as shown here) in layout.
- MB1407 I2C Address : 0101 0100
- Copyright 2019 Octavo Systems LLC

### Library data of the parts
C51 = MCD-00006: as C61 on sheet 4 - PMIC
C52 = MCD-00199: Polarized Capacitor,10uF,16V,10%,typeA; Manufacturer_Part_Number: TAJA106K016R; Manufacturer: AVX; Provided_By: Subcon; ECCN_US: EAR99; ECCN_EU: NEC
CN4 = 2-1734248-0: Socket ,TEConn,FCC/FPC, 20pins, 1.0mm,SMT, ZIF Receptacle; Internal_Part_Number: MCD-01013; Part_Type: Connector; Manufacturer: TE CONNECTIVITY; Provided_By: Subcon; Initial_Board_Reference: MB1272
H1-H4 = MCD-00035: POSITION HOLE C6D3R5; Part_Type: Mechanical; Initial_Board_Reference: mb1274
L7 = MCD-00046: SMD Chip ferrite bead, 30R@100MHz +/-30%, 5A, 10mohm DC, S (Standard) material, 0603, T=0.8mm; Part_Type: Inductor; Manufacturer_Part_Number: MPZ1608S300A; Manufacturer: TDK; Provided_By: Subcon; Initial_Board_Reference: MB1274
R11 = MCD-00053: as R84 on sheet 6 - AUDIO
